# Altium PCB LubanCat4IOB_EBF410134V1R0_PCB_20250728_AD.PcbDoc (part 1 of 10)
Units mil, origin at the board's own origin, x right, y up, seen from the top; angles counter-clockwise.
Board outline 5236.21 x 4055.11 mil, 6 copper layers (TOP, GND02, ART03, PWR04, GND05, BOTTOM), stack 47.2 mil thick; 614 components, 490 nets, 2311 pads, 1916 vias.
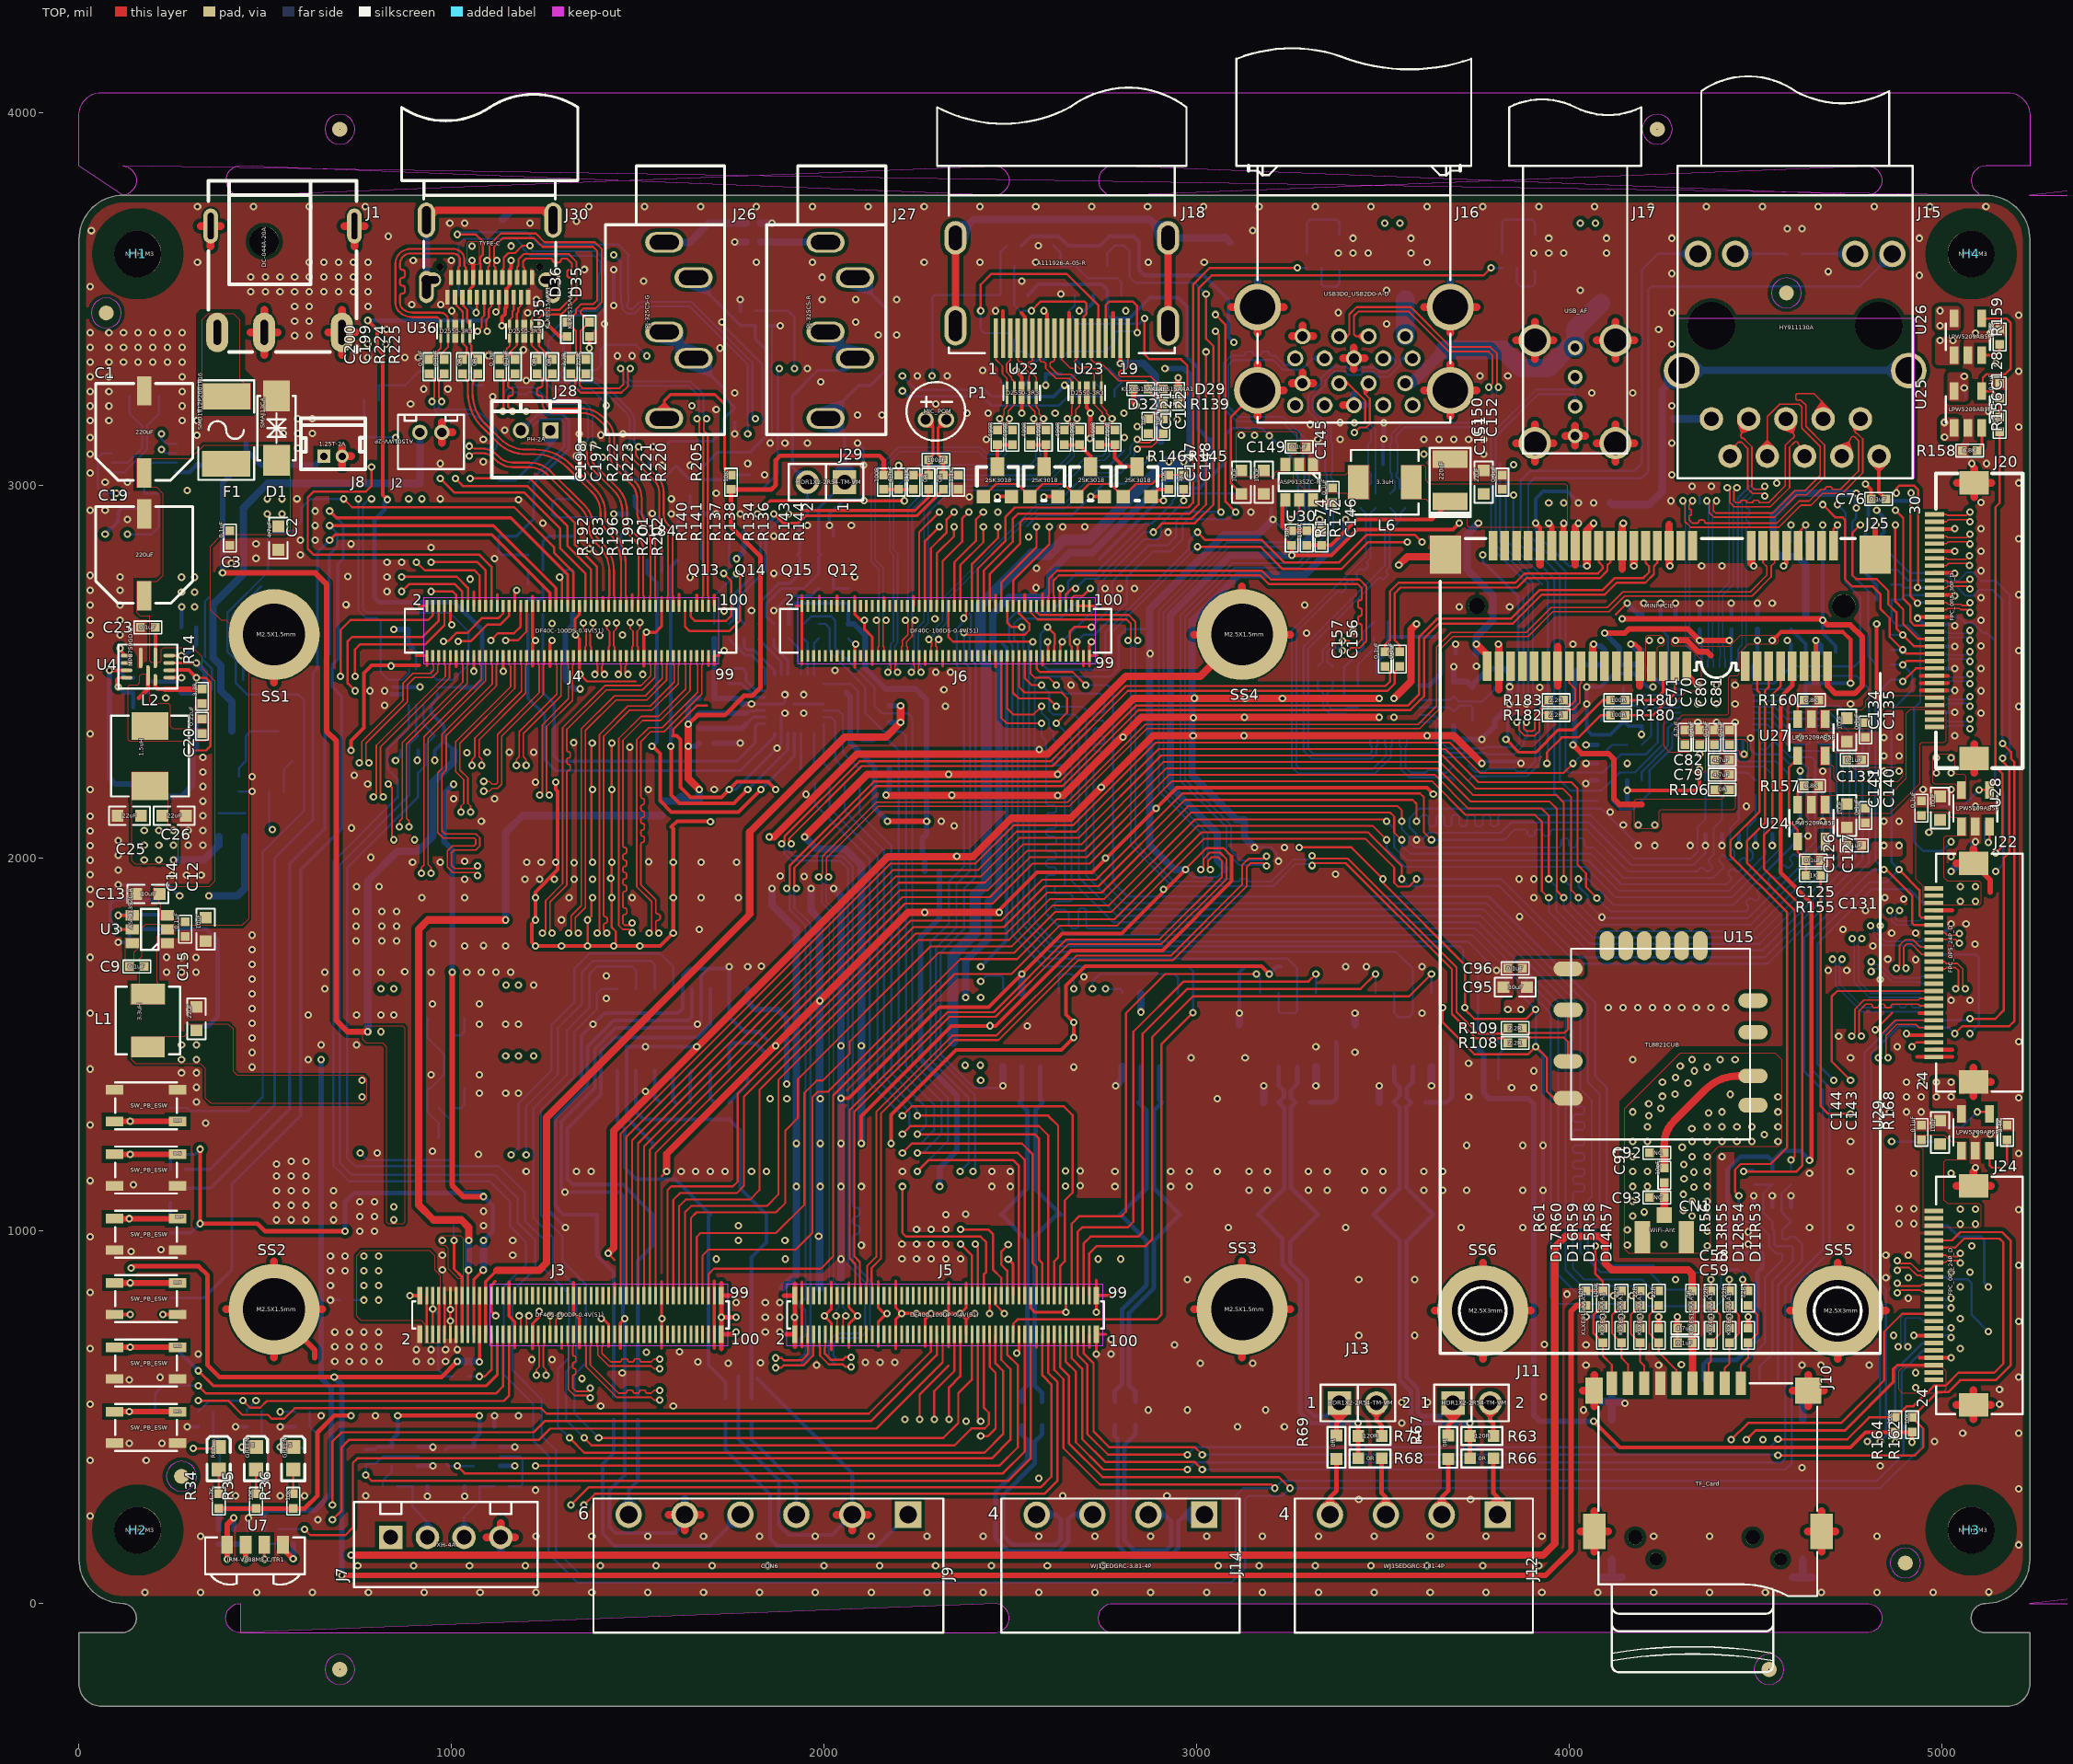
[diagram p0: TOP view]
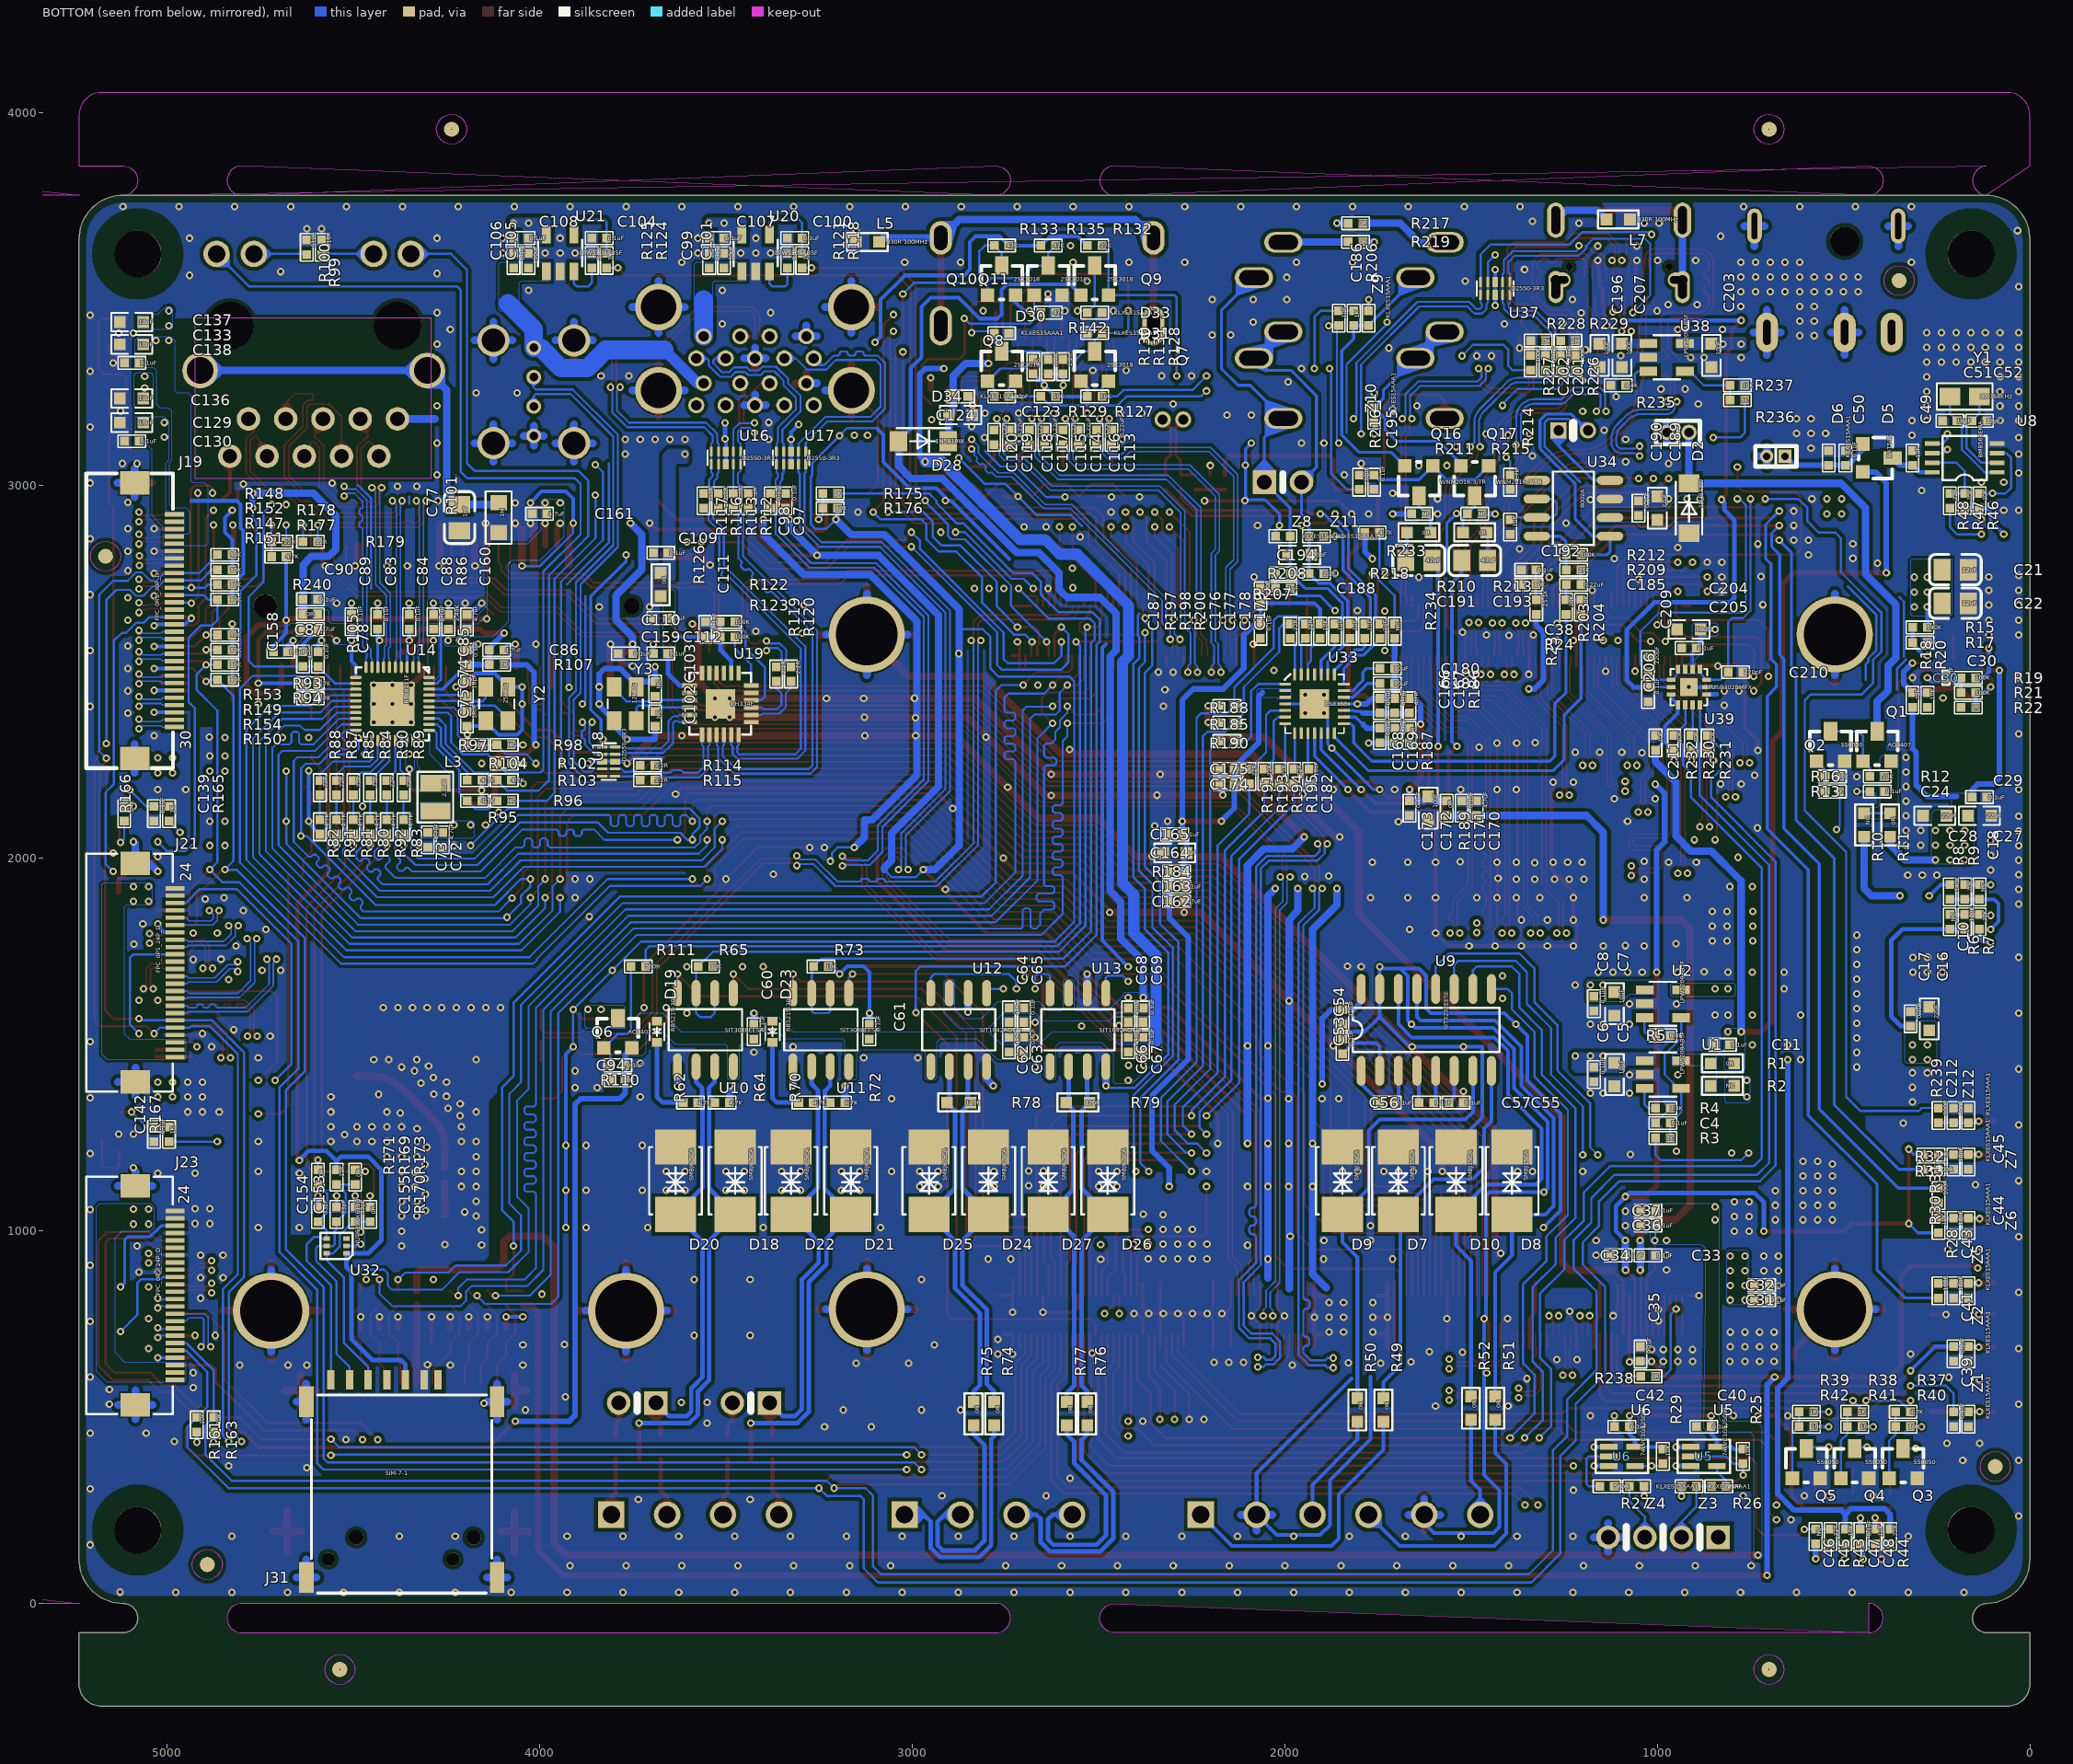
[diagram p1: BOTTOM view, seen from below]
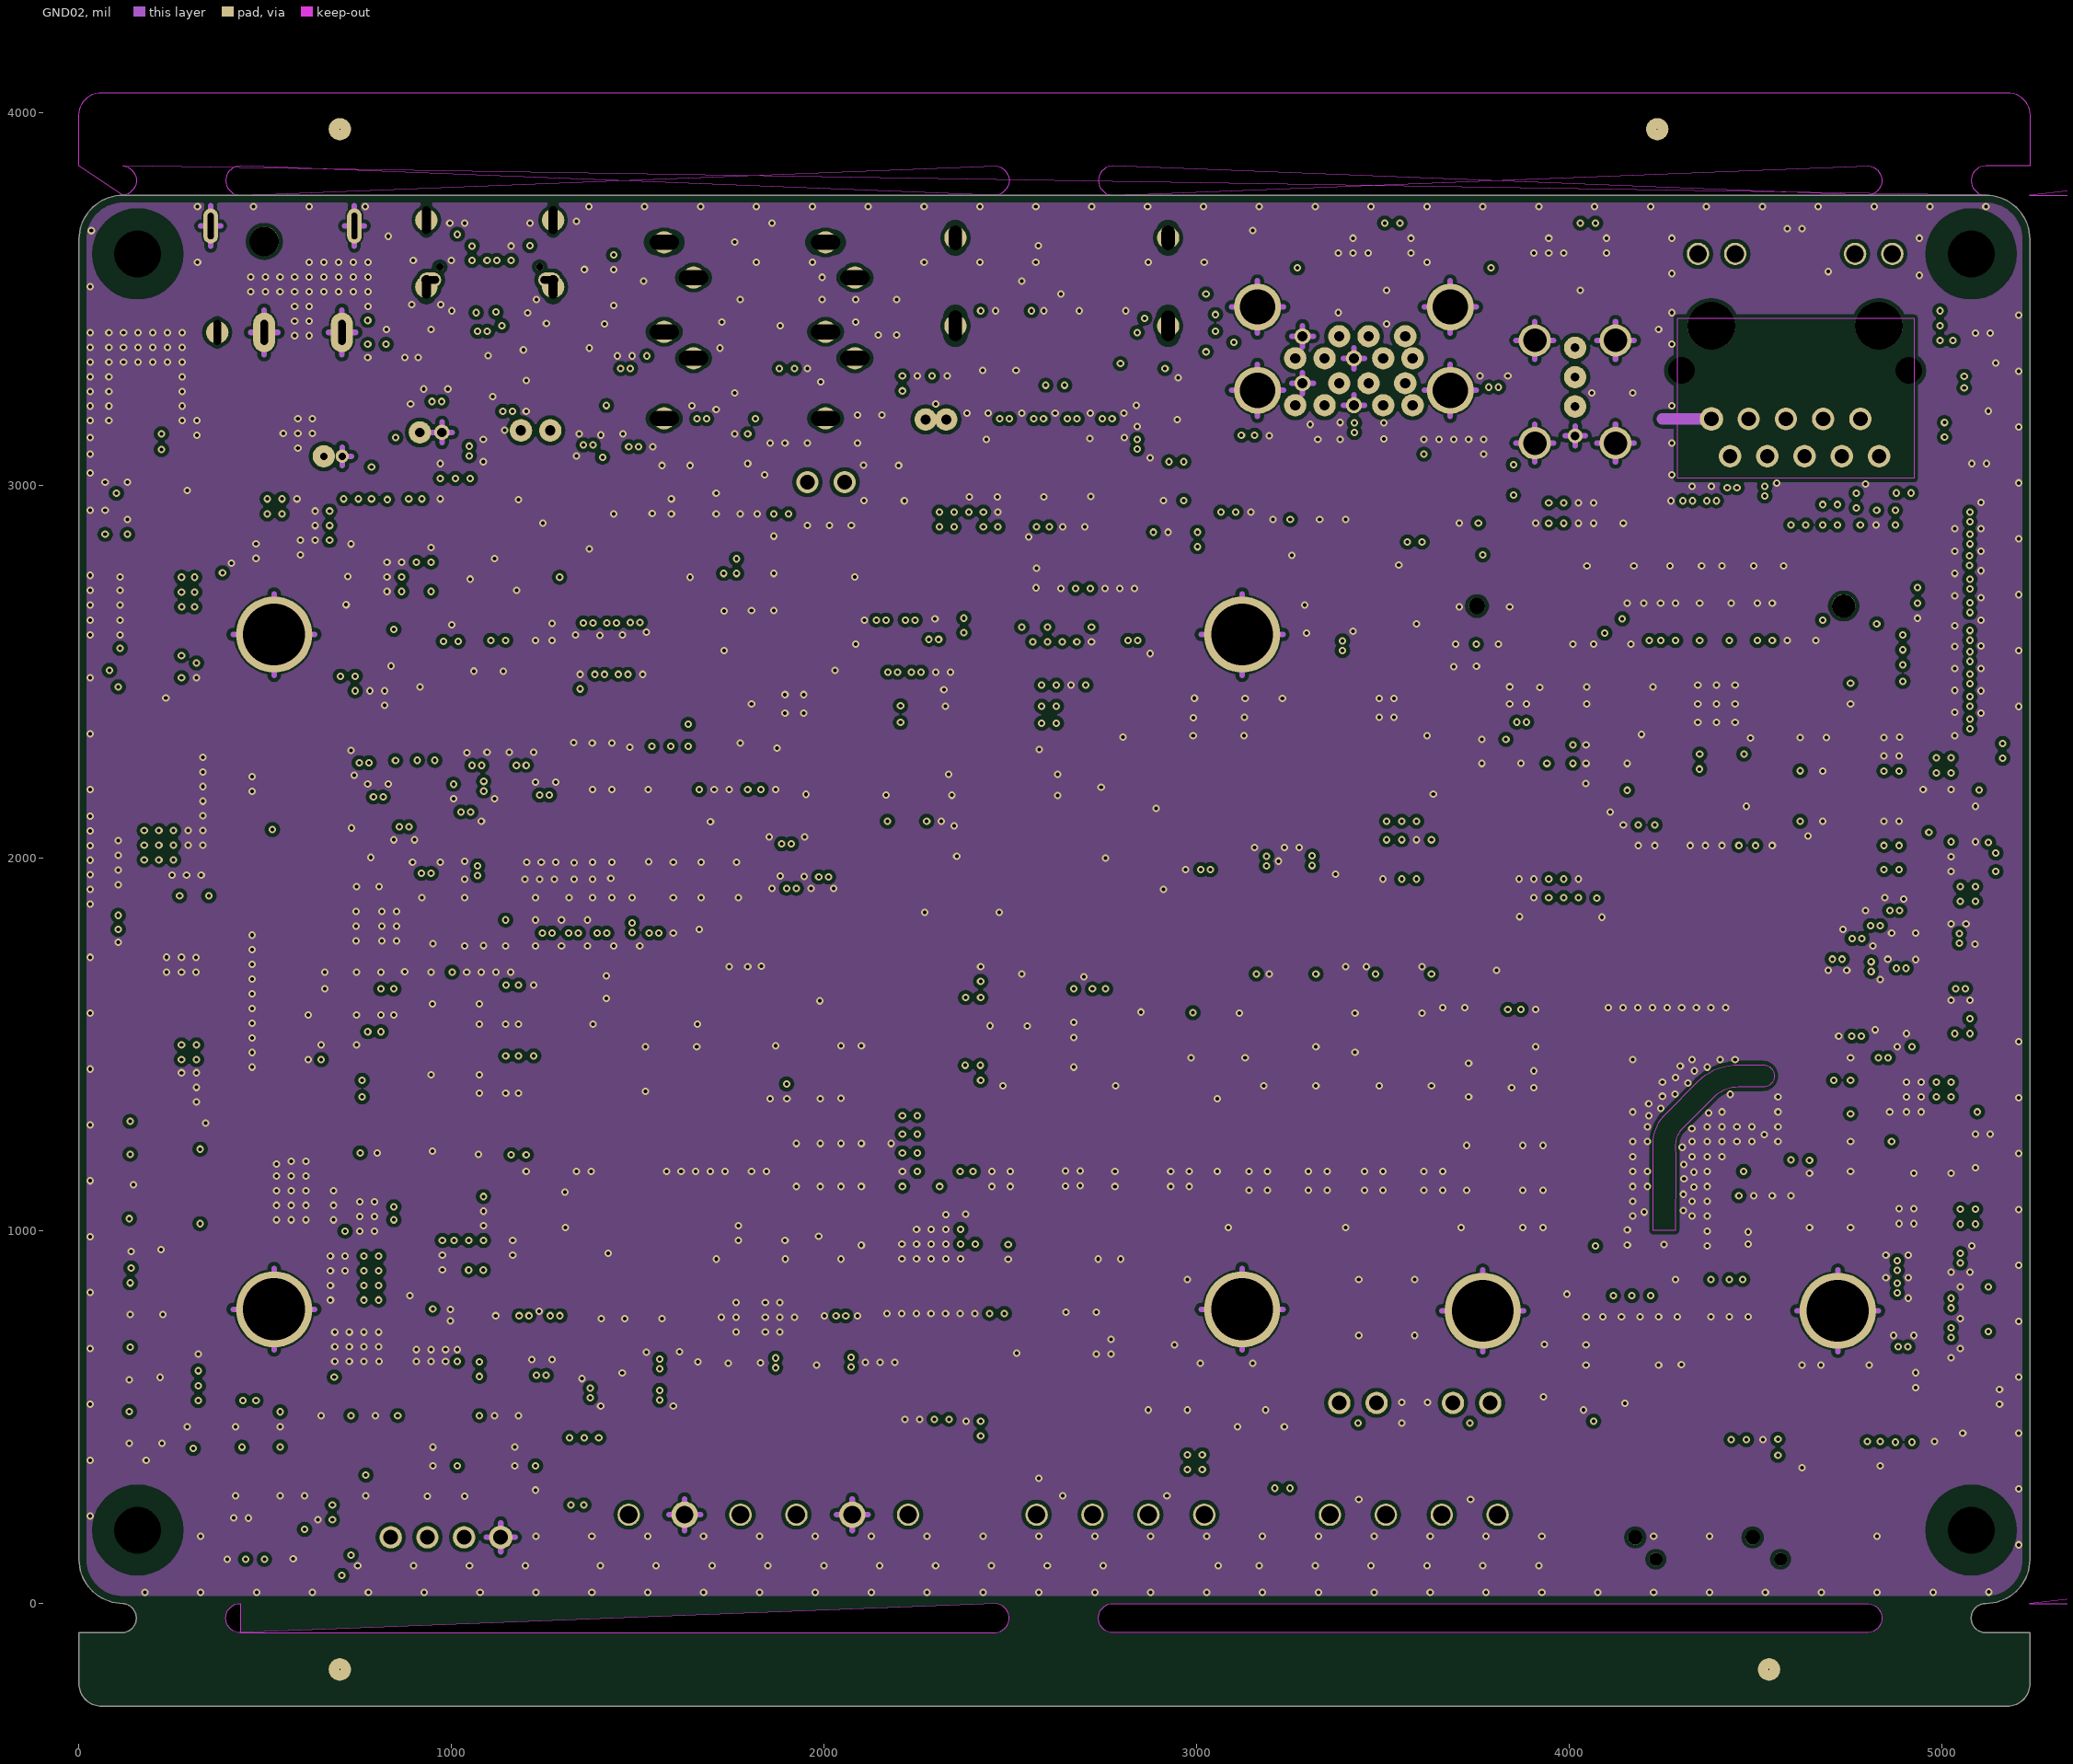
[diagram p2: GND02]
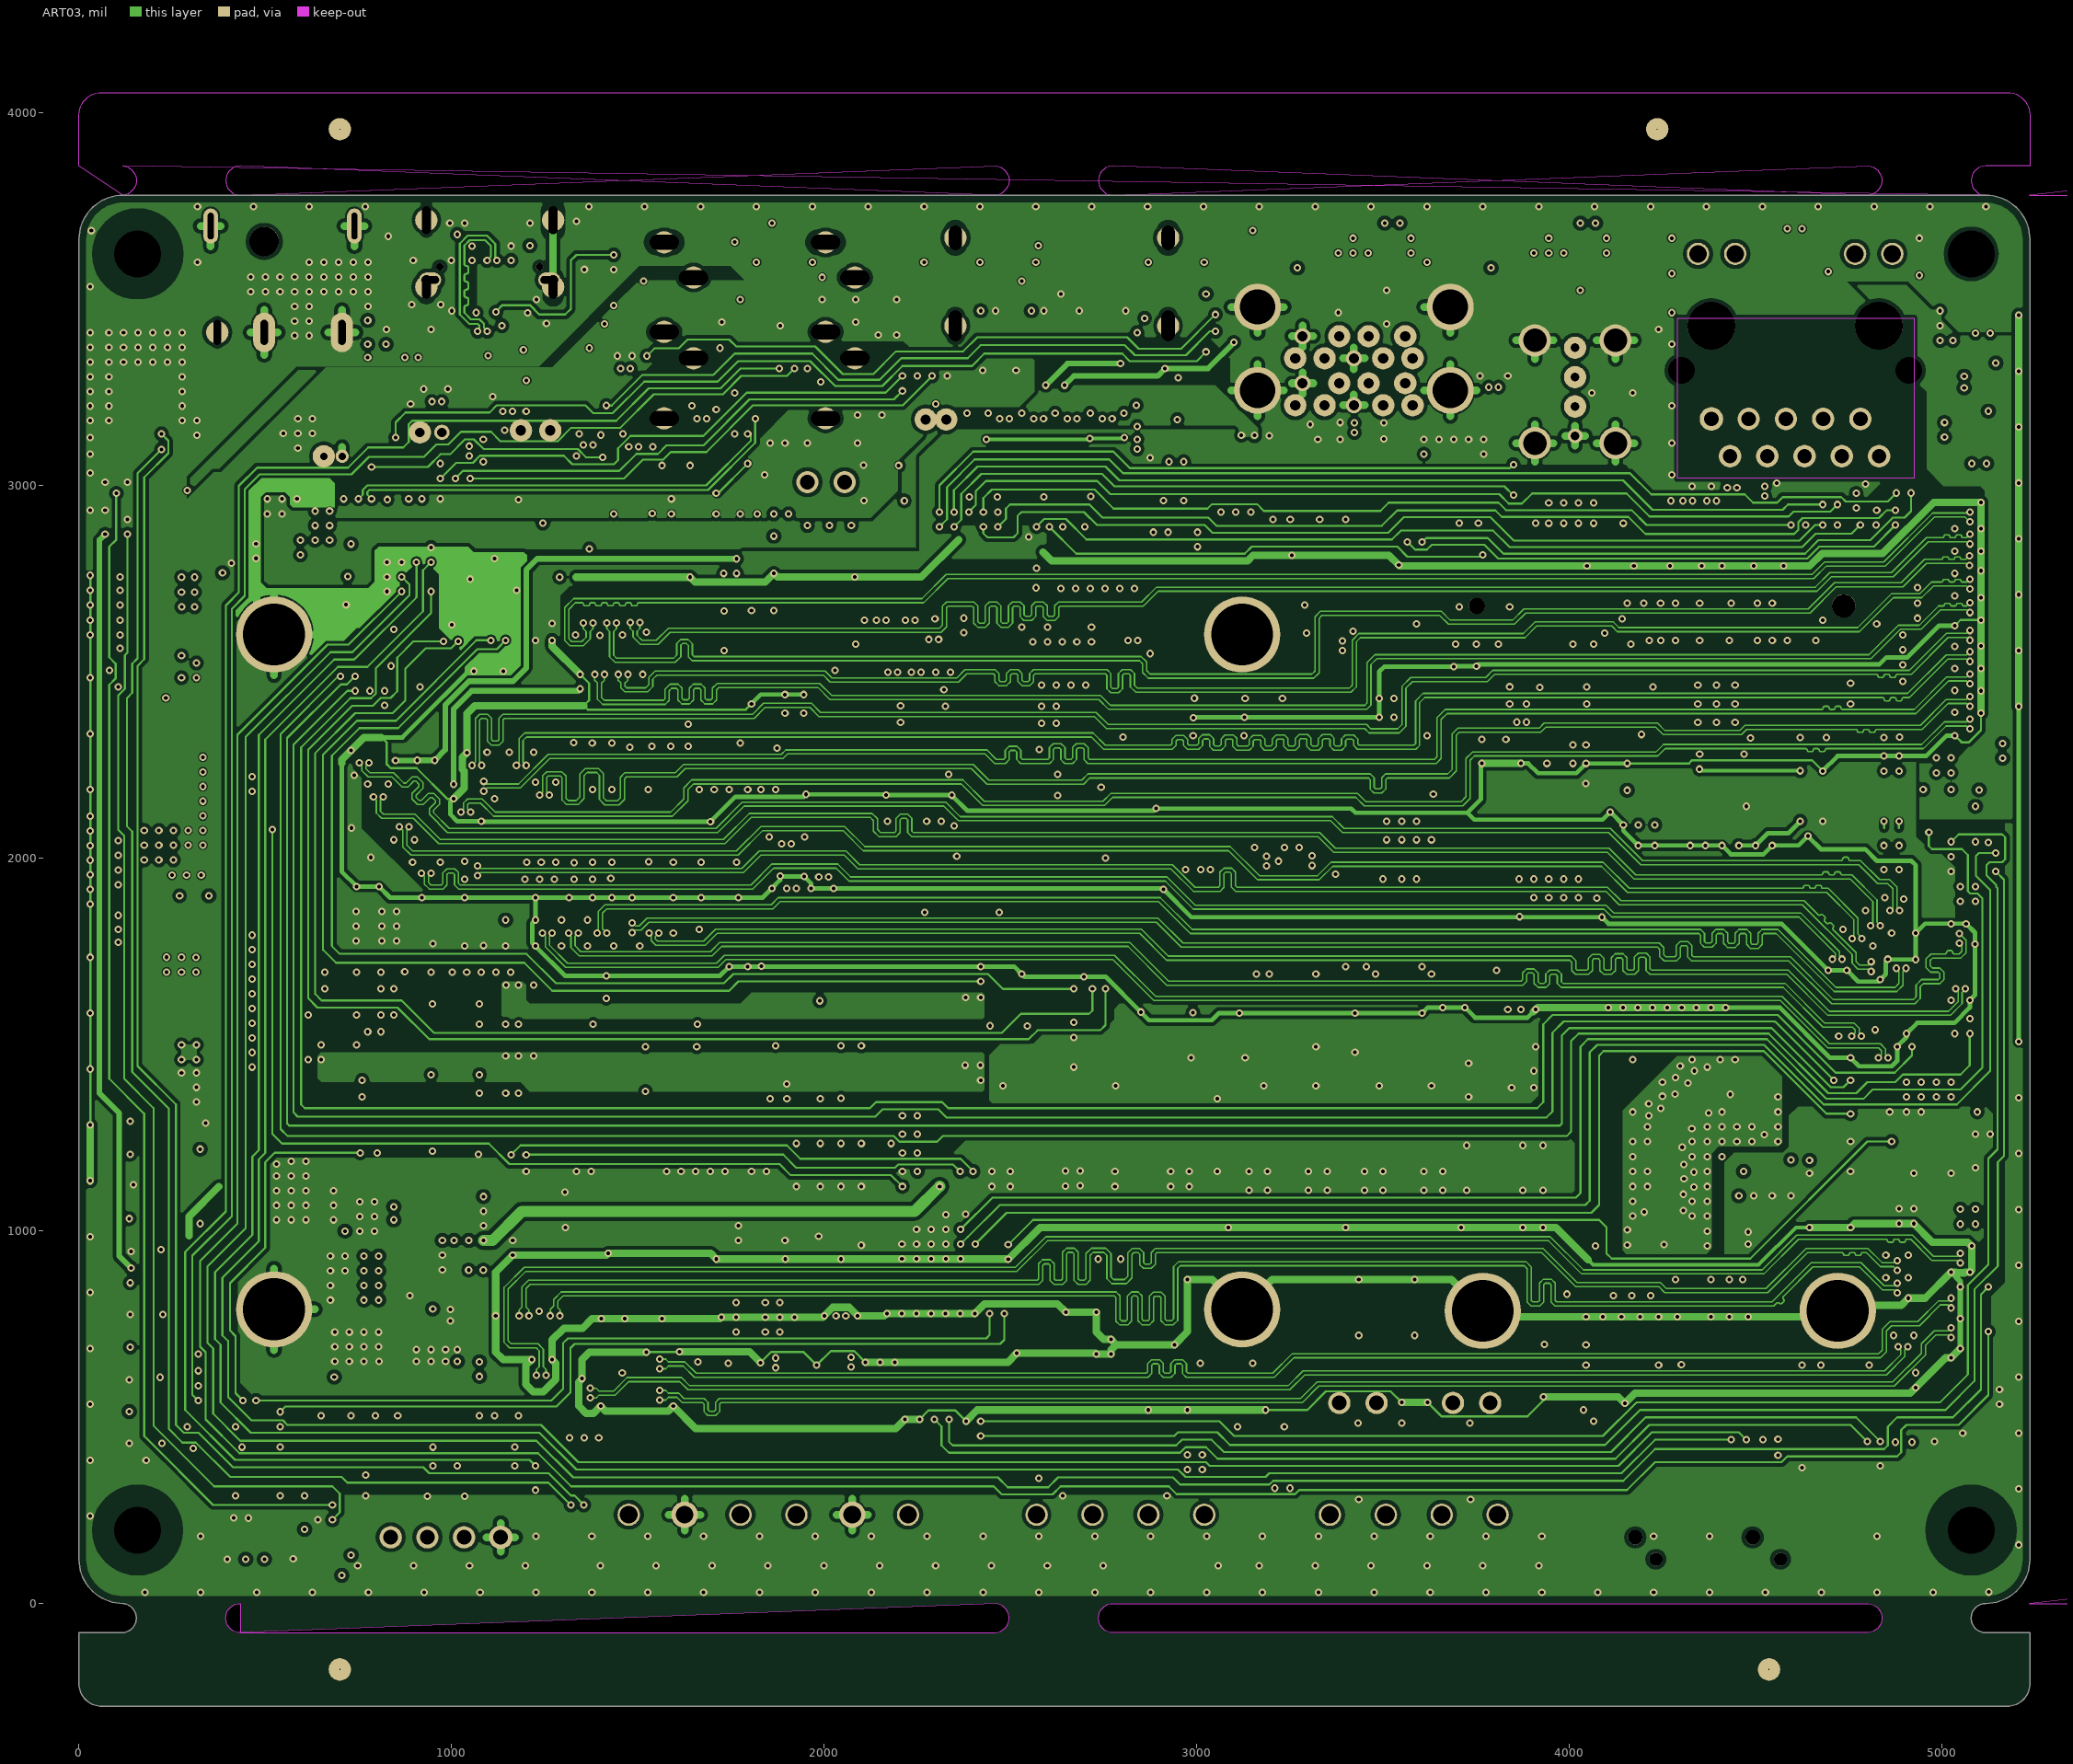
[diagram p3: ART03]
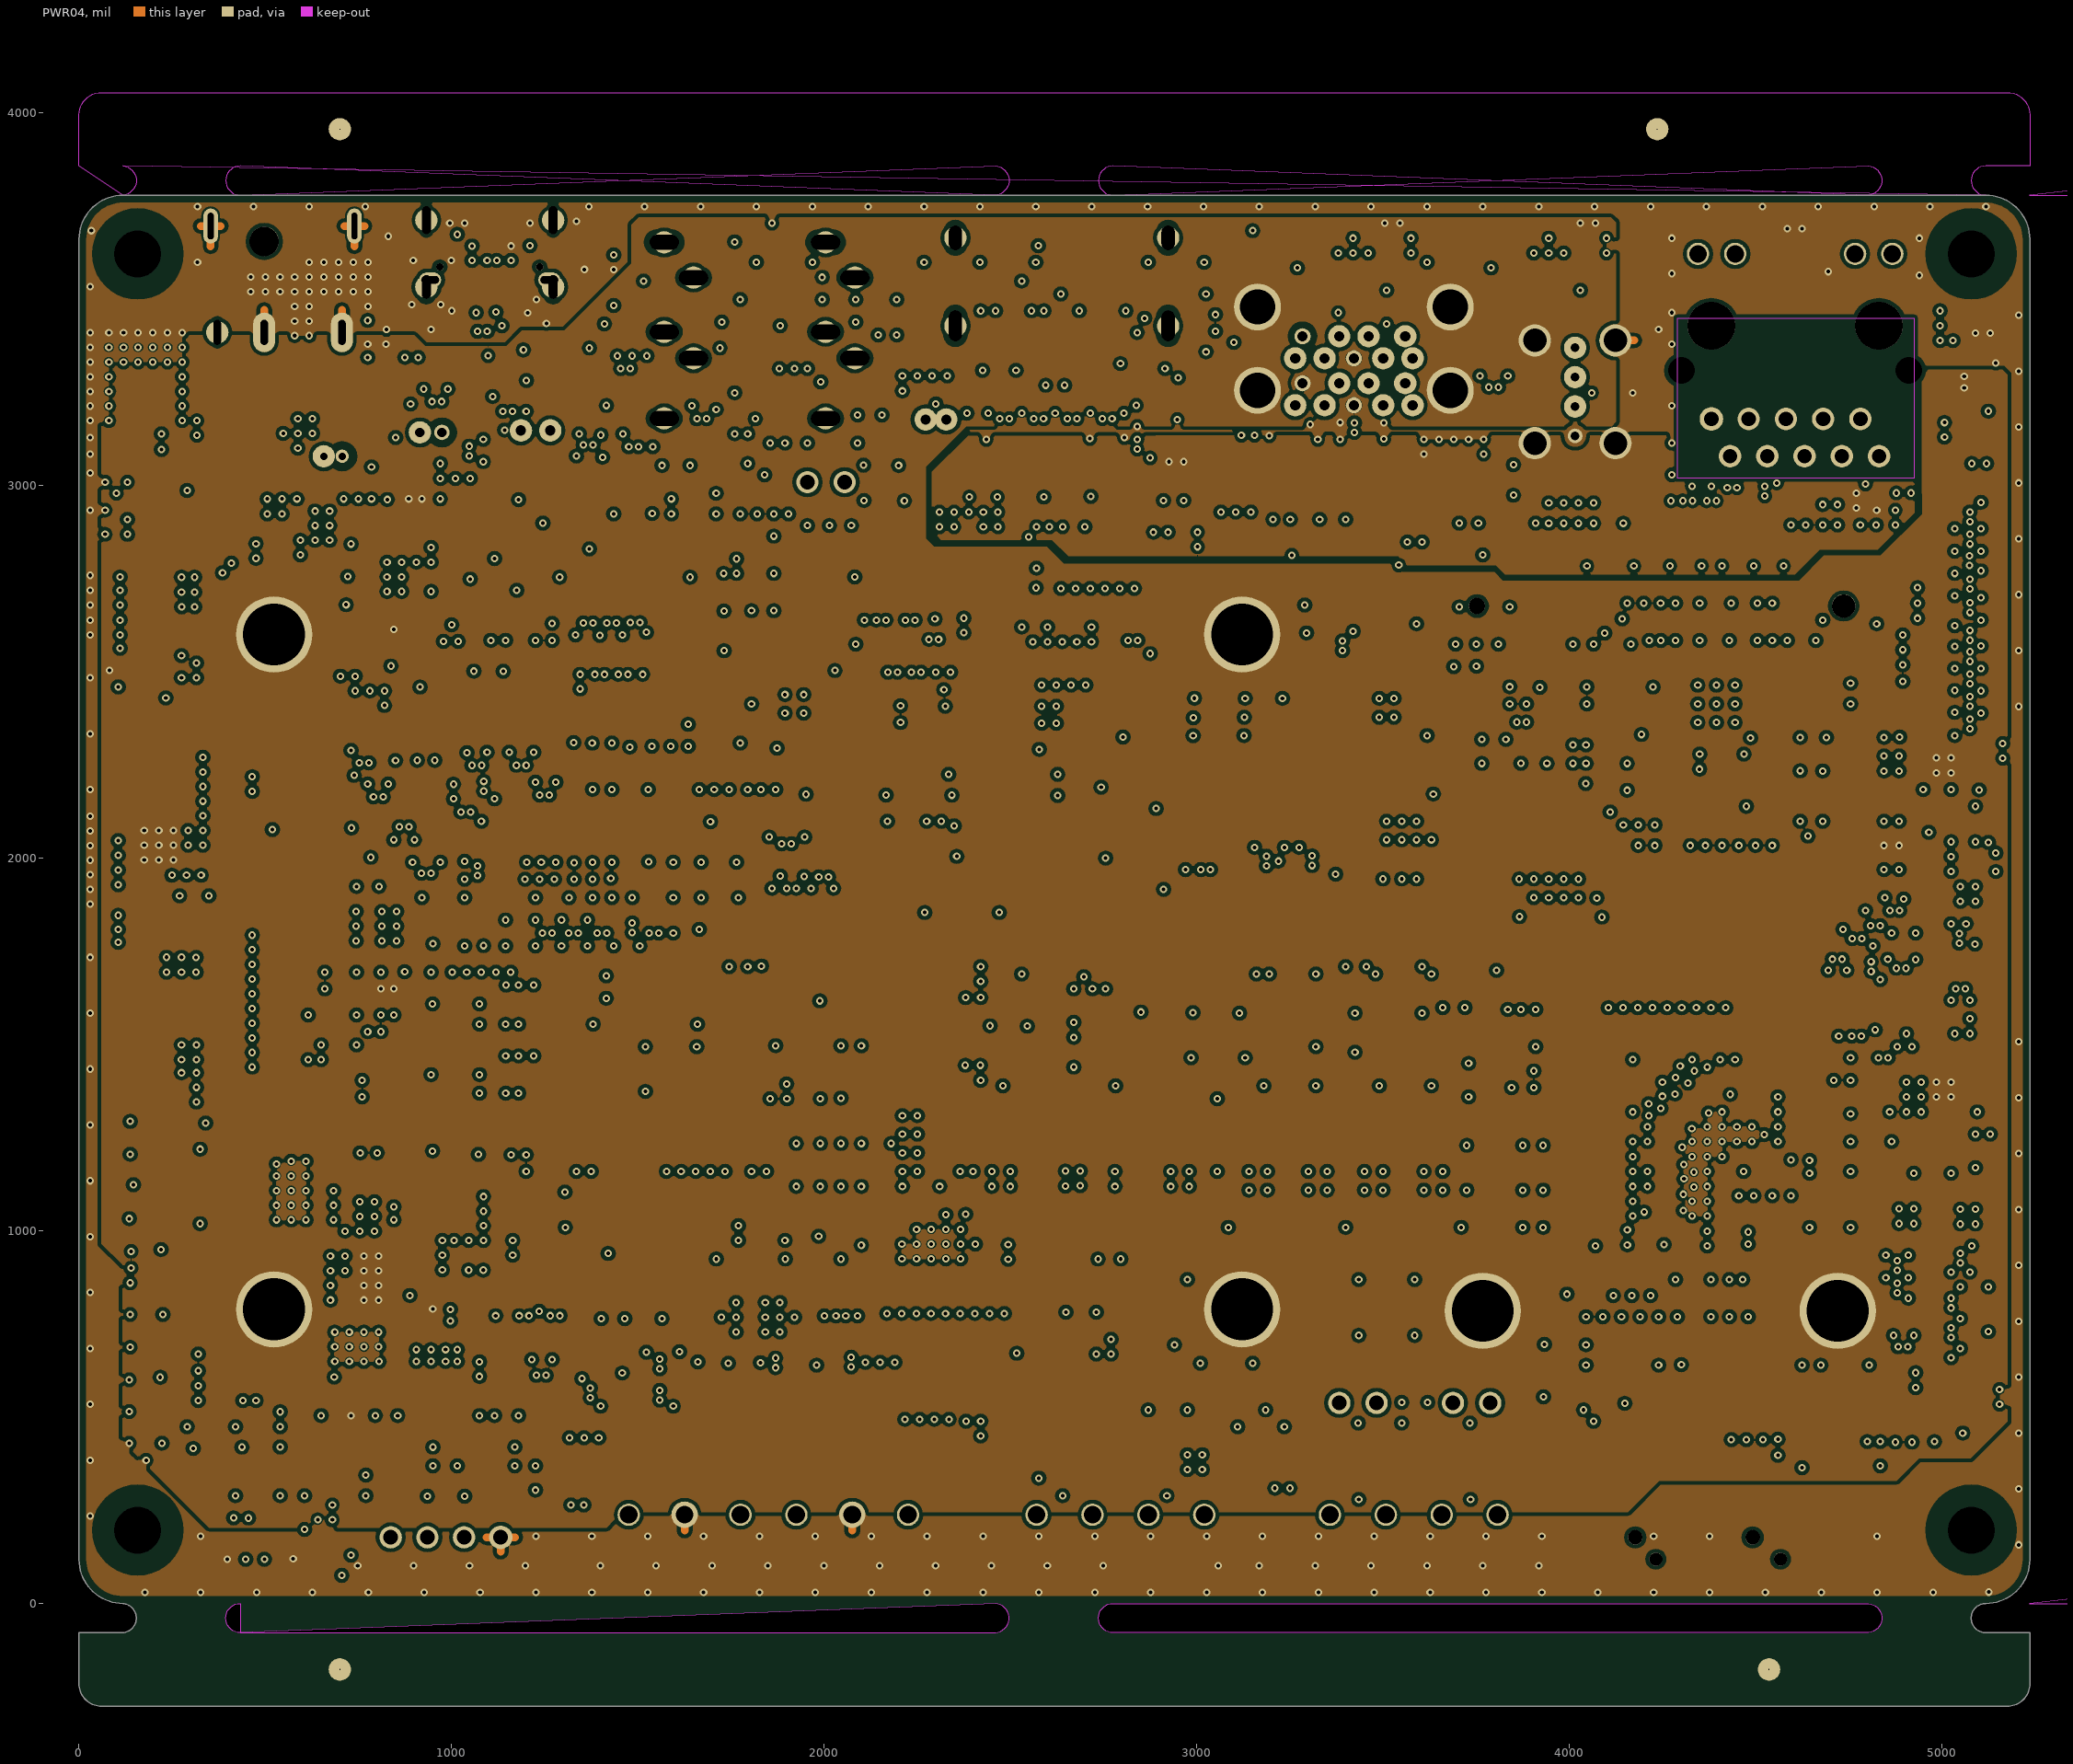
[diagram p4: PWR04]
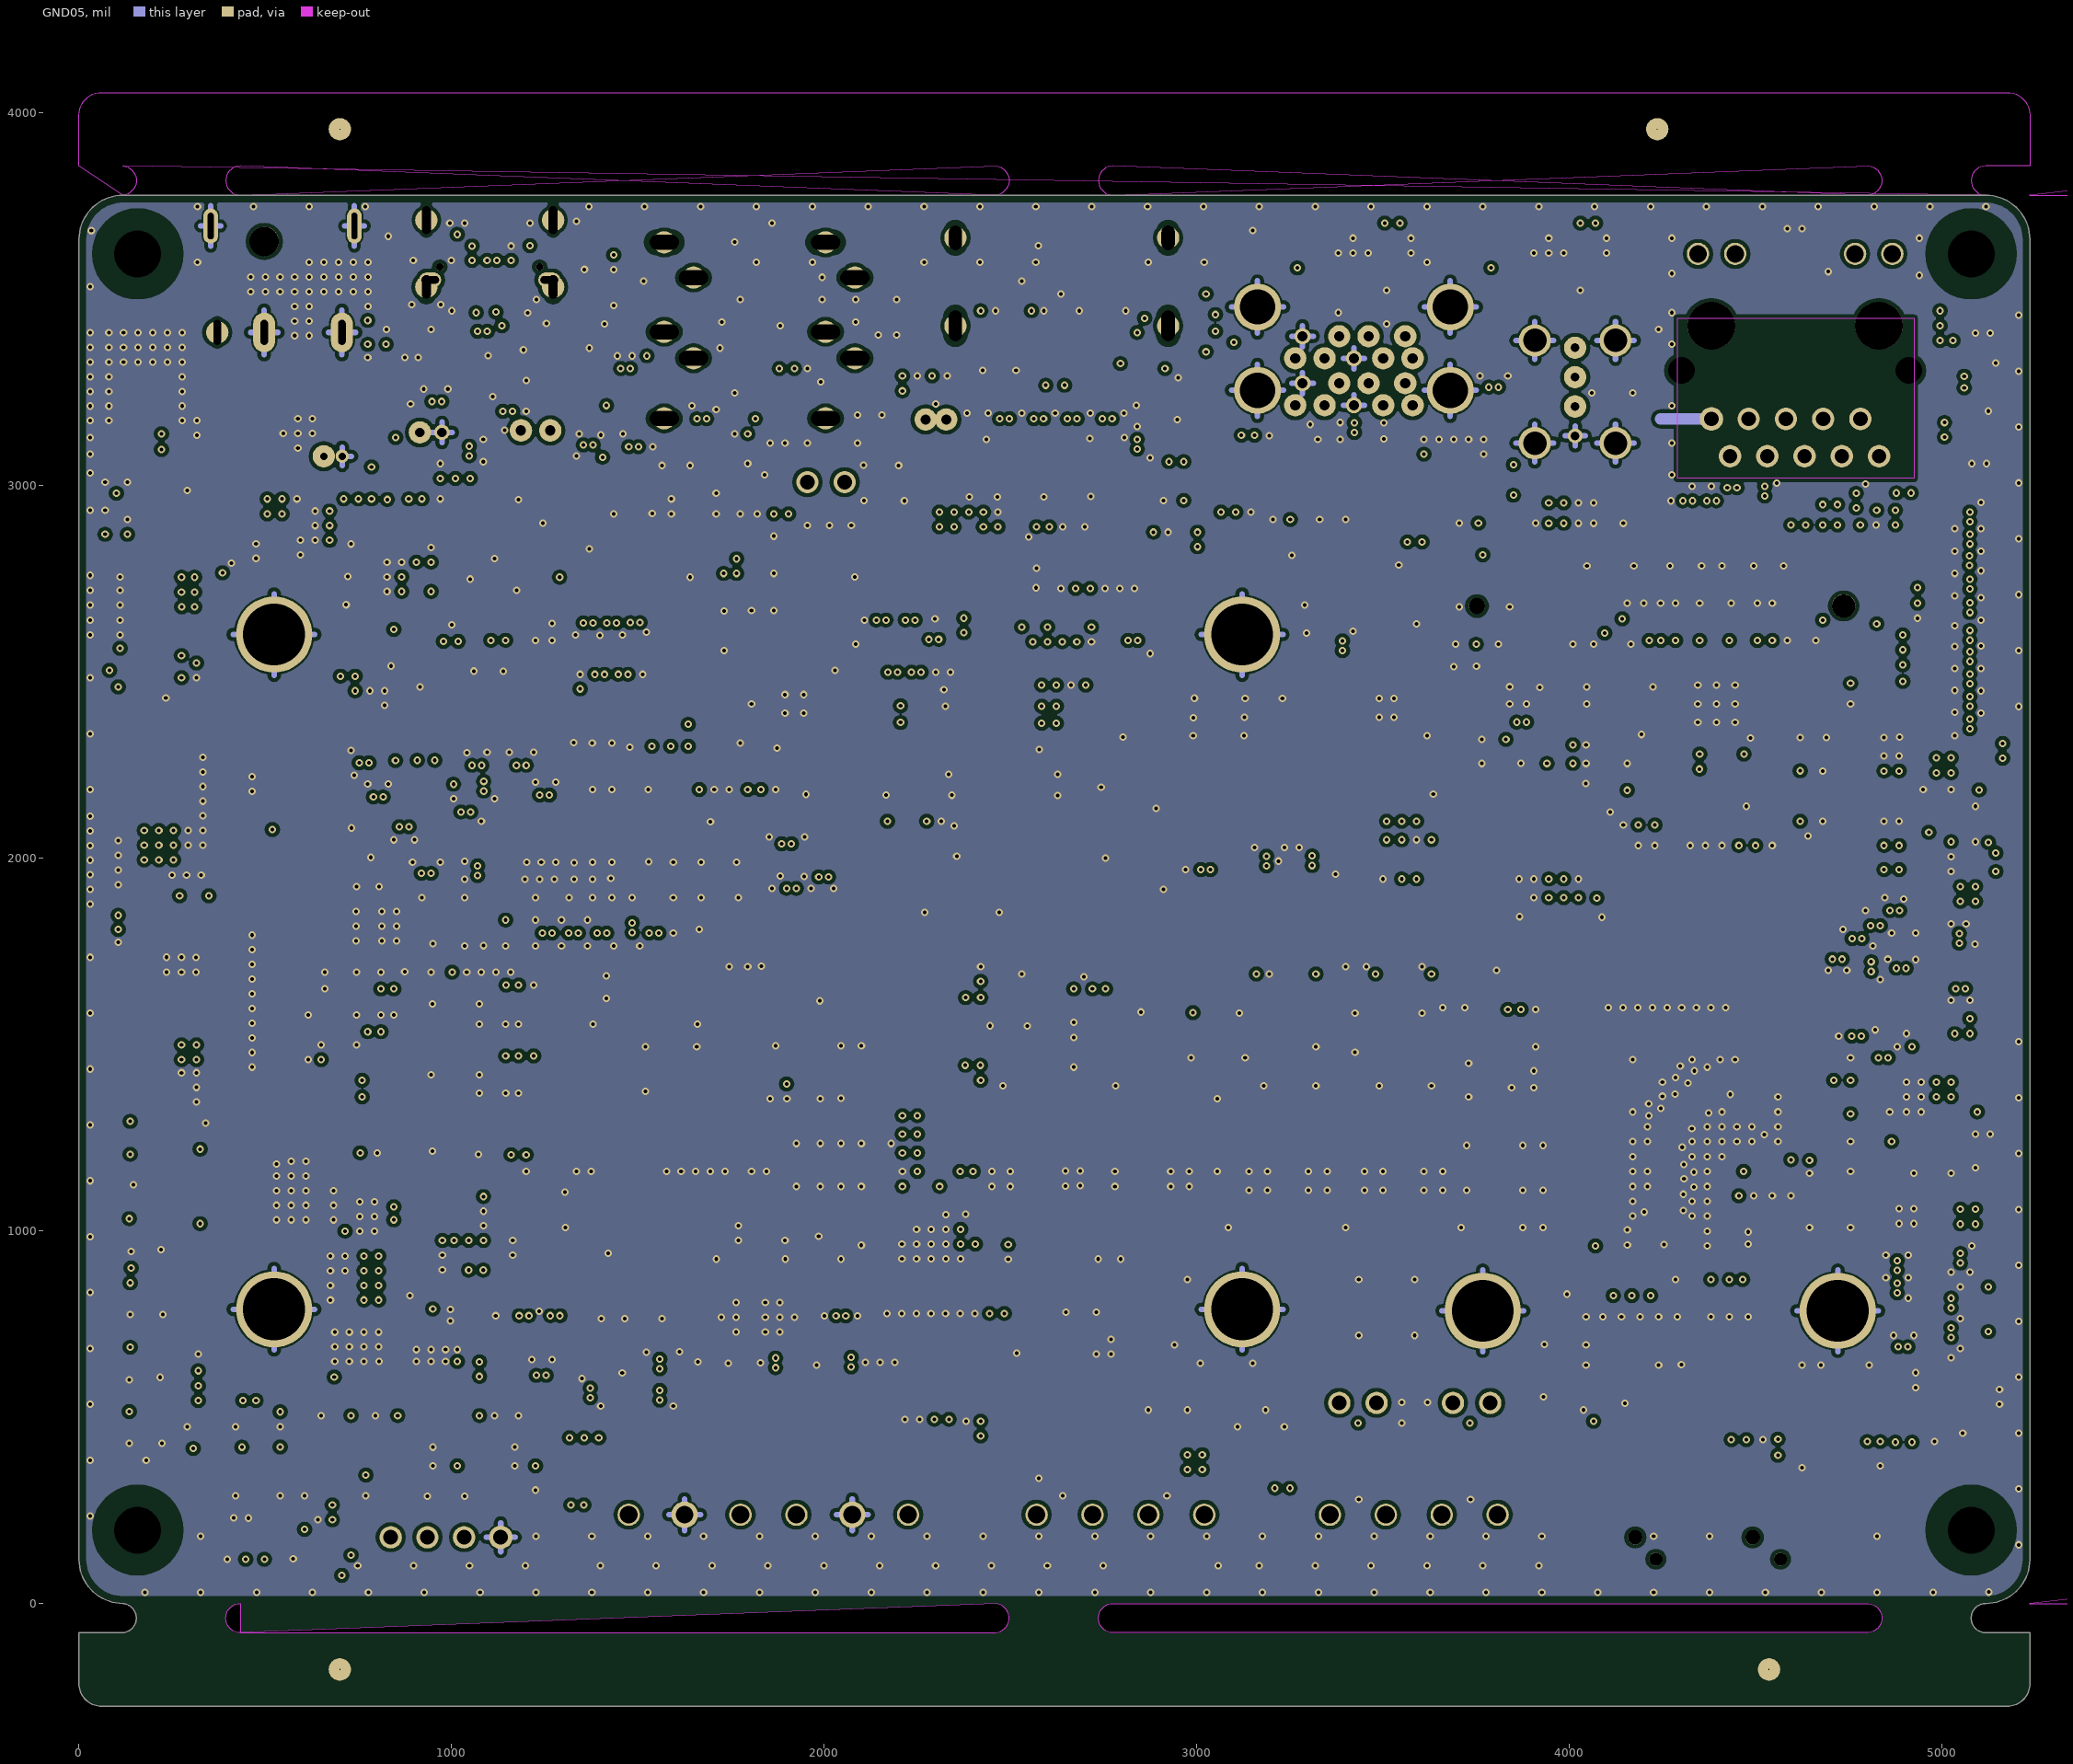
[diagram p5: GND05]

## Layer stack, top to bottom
Top Solder: solder mask 0.4, Solder Resist, Dk 3.5
TOP: signal copper 1.2
Dielectric 1: core 8, FR-4, Dk 4.5
GND02: signal copper 1.2
Dielectric2: core 8, FR-4, Dk 4.5
ART03: signal copper 1.2
Dielectric3: core 8, FR-4, Dk 4.5
PWR04: signal copper 1.2
Dielectric4: core 8, FR-4, Dk 4.5
GND05: signal copper 1.2
Dielectric5: core 8, FR-4, Dk 4.5
BOTTOM: signal copper 1.2
Bottom Solder: solder mask 0.4, Solder Resist, Dk 3.5

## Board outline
5176.21,-275.59 60,-275.59 cw(c60,-215.59) 0,-215.59 0,-78.74 118.11,-78.74 ccw(c113.95,-39.37) 118.11,0 cw(c118.11,118.11) 0,118.11 0,3661.41 cw(c118.11,3661.41) 118.11,3779.52 5118.1,3779.52 cw(c5118.1,3661.41) 5236.21,3661.41 5236.21,118.11 cw(c5118.1,118.11) 5118.1,0 ccw(c5118.1,-39.37) 5118.1,-78.74 5236.21,-78.74 5236.21,-215.59 cw(c5176.21,-215.59)
cut-out: 4803.14,3858.26 cw(c4798.98,3818.89) 2775.59,3858.26 ccw(c2775.59,3818.89)
cut-out: 2460.62,3858.26 cw(c2456.47,3818.89) 433.07,3858.26 ccw(c433.07,3818.89)
cut-out: 433.07,-78.74 cw(c433.07,-39.37) 433.07,-78.74 2460.62,-78.74 ccw(c2456.47,-39.37)
cut-out: 4803.14,0 cw(c4798.98,-39.37) 2775.59,-78.74 cw(c2775.59,-39.37)
cut-out: 118.11,3858.26 cw(c113.95,3818.89) 0,3858.26 0,3995.11 cw(c60,3995.11) 5176.21,4055.11 cw(c5176.21,3995.11) 5236.21,3858.26 5118.1,3858.26 ccw(c5118.1,3818.89)
cut-out: 5345.24,3767.56 5345.24,3791.18 5235,3779.37 6022.4,3779.37
cut-out: 5345.24,-12.44 5345.24,11.18 5235,-0.63 6022.4,-0.63

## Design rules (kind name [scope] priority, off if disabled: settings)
Clearance [All] p1: gap=10 ignorepadtopadclearanceinfootprint=FALSE except(0: Arc-Hole Track-Hole SMDPad-Hole THPad-Hole Via-Hole Fill-Hole Poly-Hole Region-Hole Text-Hole)
DiffPairsRouting [All] p1: maxlimit=10 minlimit=10 mostfreqgap=10 toplayer_minwidth=15 toplayer_maxwidth=15 toplayer_prefwidth=15 midlayer1_minwidth=15 midlayer1_maxwidth=15 midlayer1_prefwidth=15 midlayer2_minwidth=15 midlayer2_maxwidth=15 midlayer2_prefwidth=15 midlayer3_minwidth=15 midlayer3_maxwidth=15 midlayer3_prefwidth=15 midlayer4_minwidth=15 midlayer4_maxwidth=15 midlayer4_prefwidth=15 bottomlayer_minwidth=15 bottomlayer_maxwidth=15 bottomlayer_prefwidth=15 maxuncoupledlength=500
PlaneConnect [All] p1: planeconnectstyle=Direct reliefexpansion=20 reliefentries=4 reliefconductorwidth=10 reliefairgap=10
PolygonConnect [All] p1: connectstyle=Direct reliefconductorwidth=10 reliefentries=4 polygonreliefangle="90 Angle" airgapwidth=10
RoomDefinition RoomsKeepin1 [All vs False] p1: confinementstyle=ConfineIn formatcopy=TRUE lockcomponents=FALSE outline 5118.1,3739.52 5124.91,3739.22 5131.66,3738.33 5138.32,3736.86 5144.82,3734.81 5151.11,3732.2 5157.15,3729.06 5162.9,3725.39 5168.31,3721.25 5173.33,3716.64 5177.94,3711.62 5182.08,3706.21 5185.75,3700.47 5188.89,3694.42 5191.5,3688.13 5193.55,3681.63 5195.02,3674.97 5195.91,3668.22 5196.21,3661.41 5196.21,118.11 5195.91,111.3 5195.02,104.55 5193.55,97.89 5191.5,91.39 5188.89,85.1 5185.75,79.06 5182.08,73.31 5177.94,67.9 5173.33,62.88 5168.31,58.27 5162.9,54.13 5157.15,50.46 5151.11,47.32 5144.82,44.71 5138.32,42.66 5131.66,41.19 5124.91,40.3 5118.1,40 118.11,40 111.3,40.3 104.55,41.19 97.89,42.66 91.39,44.71 85.1,47.32 79.06,50.46 73.31,54.13 67.9,58.27 62.88,62.88 58.27,67.9 54.13,73.31 50.46,79.06 47.32,85.1 44.71,91.39 42.66,97.89 41.19,104.55 40.3,111.3 40,118.11 40,3661.41 40.3,3668.22 41.19,3674.97 42.66,3681.63 44.71,3688.13 47.32,3694.42 50.46,3700.47 54.13,3706.21 58.27,3711.62 62.88,3716.64 67.9,3721.25 73.31,3725.39 79.06,3729.06 85.1,3732.2 91.39,3734.81 97.89,3736.86 104.55,3738.33 111.3,3739.22 118.11,3739.52 5118.1,3739.52
RoomDefinition RoomsKeepin0 [All vs False] p2: confinementstyle=ConfineIn formatcopy=TRUE lockcomponents=FALSE outline 5118.1,3739.52 5124.91,3739.22 5131.66,3738.33 5138.32,3736.86 5144.82,3734.81 5151.11,3732.2 5157.15,3729.06 5162.9,3725.39 5168.31,3721.25 5173.33,3716.64 5177.94,3711.62 5182.08,3706.21 5185.75,3700.47 5188.89,3694.42 5191.5,3688.13 5193.55,3681.63 5195.02,3674.97 5195.91,3668.22 5196.21,3661.41 5196.21,118.11 5195.91,111.3 5195.02,104.55 5193.55,97.89 5191.5,91.39 5188.89,85.1 5185.75,79.06 5182.08,73.31 5177.94,67.9 5173.33,62.88 5168.31,58.27 5162.9,54.13 5157.15,50.46 5151.11,47.32 5144.82,44.71 5138.32,42.66 5131.66,41.19 5124.91,40.3 5118.1,40 118.11,40 111.3,40.3 104.55,41.19 97.89,42.66 91.39,44.71 85.1,47.32 79.06,50.46 73.31,54.13 67.9,58.27 62.88,62.88 58.27,67.9 54.13,73.31 50.46,79.06 47.32,85.1 44.71,91.39 42.66,97.89 41.19,104.55 40.3,111.3 40,118.11 40,3661.41 40.3,3668.22 41.19,3674.97 42.66,3681.63 44.71,3688.13 47.32,3694.42 50.46,3700.47 54.13,3706.21 58.27,3711.62 62.88,3716.64 67.9,3721.25 73.31,3725.39 79.06,3729.06 85.1,3732.2 91.39,3734.81 97.89,3736.86 104.55,3738.33 111.3,3739.22 118.11,3739.52 5118.1,3739.52
RoutingVias [All] p1: holewidth=28 width=50 viastyle="Through Hole" minholewidth=28 minwidth=50 maxholewidth=28 maxwidth=50
SolderMaskExpansion [All] p1: expansion=4 istentingtop=FALSE
Width [All] p1: maxlimit=10 minlimit=10 preferedwidth=10 impedanceprofiledriven=TRUE minimp=50.170000 maximp=63.220000 favimp=46.610000
28 further rules are at their usual default settings.

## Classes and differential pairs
net class DIFF90OHM: USB30_SSRXN USB30_SSRXP
net class DIFF85OHM: PCIE20_0_RXN PCIE20_0_RXP PCIE20_0_TXN PCIE20_0_TXP PE_TXN PE_TXP
net class C_EARTH: N15752445 N18241743 N18479746 N18480944
net class C_ANLOG: MIC1_L MIC1_R MIC2_L MIC2_R N18315822 N18315825 N18315828 N18315831 N18479761 N18479774 N18639472 N18639500 N18645225 N18645232 N18645288 N18645295 OUT1_L OUT1_R OUT2_L OUT2_R
net class DIFF100HOM: MDIN0_PHY MDIN1_PHY MDIN2_PHY MDIN3_PHY MDIP0_PHY MDIP1_PHY MDIP2_PHY MDIP3_PHY MIPI_CSI0_RX_CLK0N MIPI_CSI0_RX_CLK0P MIPI_CSI0_RX_CLK1N MIPI_CSI0_RX_CLK1P MIPI_CSI0_RX_D0N MIPI_CSI0_RX_D0P MIPI_CSI0_RX_D1N MIPI_CSI0_RX_D1P MIPI_CSI0_RX_D2N MIPI_CSI0_RX_D2P MIPI_CSI0_RX_D3N MIPI_CSI0_RX_D3P MIPI_DPHY0_RX_CLKN MIPI_DPHY0_RX_CLKP MIPI_DPHY0_RX_D0N MIPI_DPHY0_RX_D0P MIPI_DPHY0_RX_D1N MIPI_DPHY0_RX_D1P MIPI_DPHY0_RX_D2N MIPI_DPHY0_RX_D2P MIPI_DPHY0_RX_D3N MIPI_DPHY0_RX_D3P MIPI_DPHY0_TX_CLKN MIPI_DPHY0_TX_CLKP MIPI_DPHY0_TX_D0N MIPI_DPHY0_TX_D0P MIPI_DPHY0_TX_D1N MIPI_DPHY0_TX_D1P MIPI_DPHY0_TX_D2N MIPI_DPHY0_TX_D2P MIPI_DPHY0_TX_D3N MIPI_DPHY0_TX_D3P MIPI_DPHY1_RX_CLKN MIPI_DPHY1_RX_CLKP MIPI_DPHY1_RX_D0N MIPI_DPHY1_RX_D0P MIPI_DPHY1_RX_D1N MIPI_DPHY1_RX_D1P MIPI_DPHY1_RX_D2N MIPI_DPHY1_RX_D2P MIPI_DPHY1_RX_D3N MIPI_DPHY1_RX_D3P MIPI_DPHY1_TX_CLKN MIPI_DPHY1_TX_CLKP MIPI_DPHY1_TX_D0N MIPI_DPHY1_TX_D0P MIPI_DPHY1_TX_D1N MIPI_DPHY1_TX_D1P MIPI_DPHY1_TX_D2N MIPI_DPHY1_TX_D2P MIPI_DPHY1_TX_D3N MIPI_DPHY1_TX_D3P PCIE20_0_CLKN PCIE20_0_CLKP
net class GND: GND
net class 50OHM: GMAC1_MDC GMAC1_MDIO GMAC1_TXCLK GMAC1_TXD0 GMAC1_TXD1 GMAC1_TXD2 GMAC1_TXD3 GMAC1_TXEN
net class 3W: CAM0_NRST CAM1_NRST CAM2_NRST CAM3_NRST CTP0_RST CTP1_RST FAN_PWM GMAC1_RSTN LCD0_RST LCD1_RST PCIE20X1_2_PERSTN_M0 RTC_32K_IN
net class C_POWER: 1V05_AVDD_PHY 1V05_PHY 3V3_DVDD_PHY 3V3_IMAGE0 3V3_IMAGE1 3V3_WLAN 5V0_CAM0/1 5V0_CAM2/3 5V0_IMAGE0 5V0_IMAGE1 HDMI_5V N18464854 SIM_VDD USB30_VBUS VBUS_TYPEC VCC3V3_SYS VCC5V0_SYS VCC_1V8_S0 VCC_3V3_S3 VCC_3V3_SD VCC_12V VCCA1V8_CODEC VCCA3V3_CODEC VCCA_1V8_S0 VCCA_3V3_S0 VDD_3V3 VDD_5V
differential pair DIFF_SS_TX: +USB30_SSTXN -USB30_SSTXP
differential pair DIFF_USB30_SSRX: +USB30_SSRXN -USB30_SSRXP
differential pair DIFF_USB20_HOST1_D: +USB20_HOST1_DM -USB20_HOST1_DP
differential pair DP3: +USB20_HOST0_DM -USB20_HOST0_DP
differential pair DIFF_SSTX_2: +TYPEC0_SSTX2N/DP0_TX3N -TYPEC0_SSTX2P/DP0_TX3P
differential pair DIFF_SSTX_1: +TYPEC0_SSTX1N/DP0_TX1N -TYPEC0_SSTX1P/DP0_TX1P
differential pair DIFF_SSRX_2: +TYPEC0_SSRX2N/DP0_TX2N -TYPEC0_SSRX2P/DP0_TX2P
differential pair DIFF_SSRX_1: +TYPEC0_SSRX1N/DP0_TX0N -TYPEC0_SSRX1P/DP0_TX0P
differential pair DIFF_TYPEC0_AUX: +TYPEC0_SBU1/DP0_AUXP -TYPEC0_SBU2/DP0_AUXN
differential pair DIFF_OTG_D: +TYPEC0_OTG_DM -TYPEC0_OTG_DP
differential pair DIFF_TYPEC_CC: +TYPEC_CC1 -TYPEC_CC2
differential pair DIFF_HDMI_TX0_D3: +TX_D3N_PORT -TX_D3P_PORT
differential pair DIFF_HDMI_TX0_D2: +TX_D2N_PORT -TX_D2P_PORT
differential pair DIFF_HDMI_TX0_D1: +TX_D1N_PORT -TX_D1P_PORT
differential pair DIFF_HDMI_TX0_D0: +TX_D0N_PORT -TX_D0P_PORT
differential pair DIFF_SSTX_2: +SSTX_2P -TYPEC0_SSTX2N/DP0_TX3N
differential pair DIFF_SSTX_2: +SSTX_2N -SSTX_2P
differential pair DIFF_SSTX_1: +SSTX_1P -TYPEC0_SSTX1N/DP0_TX1N
differential pair DIFF_SSTX_1: +SSTX_1N -SSTX_1P
differential pair DIFF_SSRX_2: +SSRX_2P -TYPEC0_SSRX2N/DP0_TX2N
differential pair DIFF_SSRX_2: +SSRX_2N -SSRX_2P
differential pair DIFF_SSRX_1: +SSRX_1P -TYPEC0_SSRX1N/DP0_TX0N
differential pair DIFF_SSRX_1: +SSRX_1N -SSRX_1P
differential pair DIFF_SS_TX: +SS_TXP -USB30_SSTXN
differential pair DIFF_SS_TX: +SS_TXN -SS_TXP
differential pair DIFF_TYPEC0_AUX: +SBU_2 -TYPEC0_SBU1/DP0_AUXP
differential pair DIFF_TYPEC0_AUX: +SBU_1 -SBU_2
differential pair PE_TX: +PE_TXN -PE_TXP
differential pair PCIE20_0_TX: +PCIE20_0_TXN -PCIE20_0_TXP
differential pair DIFF_PCIE20_0_RX: +PCIE20_0_RXN -PCIE20_0_RXP
differential pair DIFF_PCIE20_0_CLK: +PCIE20_0_CLKN -PCIE20_0_CLKP
differential pair DIFF_OTG_D: +OTG_DP -TYPEC0_OTG_DM
differential pair DIFF_OTG_D: +OTG_DM -OTG_DP
differential pair DIFF_USB20_HOST1_D: +N18057335 -USB20_HOST1_DM
differential pair DIFF_USB20_HOST1_D: +N18057325 -N18057335
differential pair DP4: +N18057251 -N18057253
differential pair DP3: +N17770942 -USB20_HOST0_DM
differential pair DP3: +N17770939 -N17770942
differential pair DIFF_MIPI_DPHY1_TX_D3: +MIPI_DPHY1_TX_D3N -MIPI_DPHY1_TX_D3P
differential pair DIFF_MIPI_DPHY1_TX_D2: +MIPI_DPHY1_TX_D2N -MIPI_DPHY1_TX_D2P
differential pair DIFF_MIPI_DPHY1_TX_D1: +MIPI_DPHY1_TX_D1N -MIPI_DPHY1_TX_D1P
differential pair DIFF_MIPI_DPHY1_TX_D0: +MIPI_DPHY1_TX_D0N -MIPI_DPHY1_TX_D0P
differential pair DIFF_MIPI_DPHY1_TX_CLK: +MIPI_DPHY1_TX_CLKN -MIPI_DPHY1_TX_CLKP
differential pair DIFF_MIPI_DPHY1_RX_D3: +MIPI_DPHY1_RX_D3N -MIPI_DPHY1_RX_D3P
differential pair DIFF_MIPI_DPHY1_RX_D2: +MIPI_DPHY1_RX_D2N -MIPI_DPHY1_RX_D2P
differential pair DIFF_MIPI_DPHY1_RX_D1: +MIPI_DPHY1_RX_D1N -MIPI_DPHY1_RX_D1P
differential pair DIFF_MIPI_DPHY1_RX_D0: +MIPI_DPHY1_RX_D0N -MIPI_DPHY1_RX_D0P
differential pair DIFF_MIPI_DPHY1_RX_CLK: +MIPI_DPHY1_RX_CLKN -MIPI_DPHY1_RX_CLKP
differential pair DIFF_MIPI_DPHY0_TX_D3: +MIPI_DPHY0_TX_D3N -MIPI_DPHY0_TX_D3P
differential pair DIFF_MIPI_DPHY0_TX_D2: +MIPI_DPHY0_TX_D2N -MIPI_DPHY0_TX_D2P
differential pair DIFF_MIPI_DPHY0_TX_D1: +MIPI_DPHY0_TX_D1N -MIPI_DPHY0_TX_D1P
differential pair DIFF_MIPI_DPHY0_TX_D0: +MIPI_DPHY0_TX_D0N -MIPI_DPHY0_TX_D0P
differential pair DIFF_MIPI_DPHY0_TX_CLK: +MIPI_DPHY0_TX_CLKN -MIPI_DPHY0_TX_CLKP
differential pair DIFF_MIPI_DPHY0_RX_D3: +MIPI_DPHY0_RX_D3N -MIPI_DPHY0_RX_D3P
differential pair DIFF_MIPI_DPHY0_RX_D2: +MIPI_DPHY0_RX_D2N -MIPI_DPHY0_RX_D2P
differential pair DIFF_MIPI_DPHY0_RX_D1: +MIPI_DPHY0_RX_D1N -MIPI_DPHY0_RX_D1P
differential pair DIFF_MIPI_DPHY0_RX_D0: +MIPI_DPHY0_RX_D0N -MIPI_DPHY0_RX_D0P
differential pair DIFF_MIPI_DPHY0_RX_CLK: +MIPI_DPHY0_RX_CLKN -MIPI_DPHY0_RX_CLKP
differential pair DIFF_MIPI_CSI0_RX_D3: +MIPI_CSI0_RX_D3N -MIPI_CSI0_RX_D3P
differential pair DIFF_MIPI_CSI0_RX_D2: +MIPI_CSI0_RX_D2N -MIPI_CSI0_RX_D2P
differential pair DIFF_MIPI_CSI0_RX_D1: +MIPI_CSI0_RX_D1N -MIPI_CSI0_RX_D1P
differential pair DIFF_MIPI_CSI0_RX_D0: +MIPI_CSI0_RX_D0N -MIPI_CSI0_RX_D0P
differential pair DIFF_MIPI_CSI0_RX_CLK1: +MIPI_CSI0_RX_CLK1N -MIPI_CSI0_RX_CLK1P
differential pair DIFF_MIPI_CSI0_RX_CLK0: +MIPI_CSI0_RX_CLK0N -MIPI_CSI0_RX_CLK0P
differential pair DIFF_MDI3_PHY: +MDIN3_PHY -MDIP3_PHY
differential pair DIFF_MDI2_PHY: +MDIN2_PHY -MDIP2_PHY
differential pair DIFF_MDI1_PHY: +MDIN1_PHY -MDIP1_PHY
differential pair DIFF_MID0_PHY: +MDIN0_PHY -MDIP0_PHY
differential pair DP4: +HUB_DP4 -N18057251
differential pair DP4: +HUB_DM4 -HUB_DP4
differential pair DP5: +HUB_DM3 -HUB_DP3
differential pair DP2: +HUB_DM2 -HUB_DP2
differential pair DP1: +HUB_DM1 -HUB_DP1
differential pair DIFF_HDMI_TX0_SBD: +HDMI_TX0_SBDN -HDMI_TX0_SBDP
differential pair DIFF_HDMI_TX0_D3: +HDMI_TX0_D3P -TX_D3N_PORT
differential pair DIFF_HDMI_TX0_D3: +HDMI_TX0_D3N -HDMI_TX0_D3P
differential pair DIFF_HDMI_TX0_D2: +HDMI_TX0_D2P -TX_D2N_PORT
differential pair DIFF_HDMI_TX0_D2: +HDMI_TX0_D2N -HDMI_TX0_D2P
differential pair DIFF_HDMI_TX0_D1: +HDMI_TX0_D1P -TX_D1N_PORT
differential pair DIFF_HDMI_TX0_D1: +HDMI_TX0_D1N -HDMI_TX0_D1P
differential pair DIFF_HDMI_TX0_D0: +HDMI_TX0_D0P -TX_D0N_PORT
differential pair DIFF_HDMI_TX0_D0: +HDMI_TX0_D0N -HDMI_TX0_D0P
differential pair DIFF_HDMI_TX0_SBD: +HDMI_EARC+ -HDMI_TX0_SBDN
differential pair DIFF_HDMI_TX0_SBD: +HDMI_EARC- -HDMI_EARC+
differential pair DP5: +B_DP3 -HUB_DM3
differential pair DP2: +B_DP2 -HUB_DM2
differential pair DP1: +B_DP1 -HUB_DM1
differential pair DP5: +B_DM3 -B_DP3
differential pair DP2: +B_DM2 -B_DP2
differential pair DP1: +B_DM1 -B_DP1

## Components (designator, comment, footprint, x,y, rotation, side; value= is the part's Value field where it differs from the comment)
C1 "CAP_EC6P3_220UF" EC6P3 175,3144.37 r180 top
C2 "CAP_NP_C0603_DISCRETE_4.7UF" C0603#1 535,2859.37 r270 top
C3 "CAP_NP_C0402_DISCRETE_0.1UF" C0402#1 405,2859.37 r270 top
C4 "CAP_NP_C0402_DISCRETE_0.1UF" C0402#1 985,1289.37 r0 bottom
C5 "CAP_NP_C0603_DISCRETE_10UF" C0603#1 1115,1419.37 r270 bottom
C6 "CAP_NP_C0402_DISCRETE_0.1UF" C0402#1 1170,1419.37 r270 bottom
C7 "CAP_NP_C0603_DISCRETE_10UF" C0603#1 1115,1609.37 r270 bottom
C8 "CAP_NP_C0402_DISCRETE_0.1UF" C0402#1 1170,1609.37 r270 bottom
C9 "CAP_NP_C0402_DISCRETE_0.1UF" C0402#1 155,1709.37 r0 top
C10 "CAP_NP_C0402_DISCRETE_NC" C0402#1 215,1829.37 r90 bottom
C11 "CAP_NP_C0402_DISCRETE_0.1UF" C0402#1 825,1499.37 r0 bottom
C12 "CAP_NP_C0603_DISCRETE_10UF" C0603#1 340,1809.37 r270 top
C13 "CAP_NP_C0603_DISCRETE_10UF" C0603#1 185,1904.37 r180 top
C14 "CAP_NP_C0402_DISCRETE_0.1UF" C0402#1 285,1809.37 r270 top
C15 "CAP_NP_C0603_DISCRETE_22UF" C0603#1 315,1569.37 r90 top
C16 "CAP_NP_C0603_DISCRETE_22UF" C0603#1 270,1569.37 r90 bottom
C17 "CAP_NP_C0402_DISCRETE_0.1UF" C0402#1 320,1569.37 r90 bottom
C18 "CAP_NP_C0402_DISCRETE_NC" C0402#1 135,1909.37 r270 bottom
C19 "CAP_EC6P3_220UF" EC6P3 175,2814.37 r180 top
C20 "CAP_NP_C0402_DISCRETE_0.22UF" C0402#1 330,2354.37 r270 top
C21 "CAP_NP_C0805_DISCRETE_22UF" C0805#1 200,2774.37 r0 bottom
C22 "CAP_NP_C0805_DISCRETE_22UF" C0805#1 200,2684.37 r0 bottom
C23 "CAP_NP_C0402_DISCRETE_0.1UF" C0402#1 185,2619.37 r180 top
C24 "CAP_NP_C0402_DISCRETE_0.1UF" C0402#1 410,2179.37 r0 bottom
C25 "CAP_NP_C0603_DISCRETE_22UF" C0603#1 135,2114.37 r180 top
C26 "CAP_NP_C0603_DISCRETE_22UF" C0603#1 255,2114.37 r0 top
C27 "CAP_NP_C0603_DISCRETE_22UF" C0603#2 135,2114.37 r0 bottom
C28 "CAP_NP_C0603_DISCRETE_22UF" C0603#1 255,2114.37 r0 bottom
C29 "CAP_NP_C0402_DISCRETE_0.1UF" C0402#2 135,2164.37 r0 bottom
C30 "CAP_NP_C0201_DISCRETE_1UF" C0201 225,2484.37 r90 bottom
C31 "CAP_NP_C0402_DISCRETE_0.1UF" C0402#2 720,814.37 r0 bottom
C32 "CAP_NP_C0402_DISCRETE_0.1UF" C0402#2 720,854.37 r0 bottom
C33 "CAP_NP_C0402_DISCRETE_0.1UF" C0402#2 1025,934.37 r0 bottom
C34 "CAP_NP_C0402_DISCRETE_0.1UF" C0402#1 1105,934.37 r0 bottom
C35 "CAP_NP_C0402_DISCRETE_0.1UF" C0402#1 1045,669.37 r90 bottom
C36 "CAP_NP_C0402_DISCRETE_0.1UF" C0402#1 1025,1014.37 r0 bottom
C37 "CAP_NP_C0402_DISCRETE_0.1UF" C0402#1 1025,1054.37 r0 bottom
C38 "CAP_NP_C0402_DISCRETE_0.1UF" C0402#1 1345,2774.37 r0 bottom
C39 "CAP_NP_C0402_DISCRETE_0.1UF" C0402#1 205,494.37 r270 bottom
C40 "CAP_NP_C0402_DISCRETE_0.1UF" C0402#1 875,474.37 r0 bottom
C41 "CAP_NP_C0402_DISCRETE_0.1UF" C0402#1 205,670 r270 bottom
C42 "CAP_NP_C0402_DISCRETE_0.1UF" C0402#1 1095,474.37 r0 bottom
C43 "CAP_NP_C0402_DISCRETE_10NF" C0402#1 205,839.37 r270 bottom
C44 "CAP_NP_C0402_DISCRETE_10NF" C0402#1 205,1014.37 r270 bottom
C45 "CAP_NP_C0402_DISCRETE_10NF" C0402#1 205,1185 r270 bottom
C46 "CAP_NP_C0402_DISCRETE_NC" C0402#1 575,179.37 r270 bottom
C47 "CAP_NP_C0402_DISCRETE_0.1UF" C0402#1 455,179.37 r90 bottom
C48 "CAP_NP_C0402_DISCRETE_1UF" C0402#1 415,179.37 r90 bottom
C49 "CAP_NP_C0402_DISCRETE_1UF" C0402#1 315,3074.37 r90 bottom
C50 "CAP_NP_C0402_DISCRETE_0.1UF" C0402#1 495,3074.37 r90 bottom
C51 "CAP_NP_C0402_DISCRETE_18PF" C0402#1 215,3174.37 r0 bottom
C52 "CAP_NP_C0402_DISCRETE_18PF" C0402#2 135,3174.37 r0 bottom
C53 "CAP_NP_C0402_DISCRETE_0.1UF" C0402#1 1845,1494.37 r90 bottom
C54 "CAP_NP_C0402_DISCRETE_4.7UF" C0402#1 1845,1574.37 r270 bottom
C55 "CAP_NP_C0402_DISCRETE_0.1UF" C0402#2 1540,1344.37 r0 bottom
C56 "CAP_NP_C0402_DISCRETE_0.1UF" C0402#1 1725,1344.37 r0 bottom
C57 "CAP_NP_C0402_DISCRETE_0.1UF" C0402#1 1620,1344.37 r0 bottom
C58 "CAP_NP_C0402_DISCRETE_4.7UF" C0402#1 4310,739.37 r180 top
C59 "CAP_NP_C0402_DISCRETE_0.1UF" C0402#1 4310,699.37 r180 top
C60 "CAP_NP_C0402_DISCRETE_0.1UF" C0402#1 3425,1534.37 r90 bottom
C61 "CAP_NP_C0402_DISCRETE_0.1UF" C0402#1 3115,1534.37 r90 bottom
C62 "CAP_NP_C0402_DISCRETE_4.7UF" C0402#1 2740,1499.37 r90 bottom
C63 "CAP_NP_C0402_DISCRETE_0.1UF" C0402#1 2700,1499.37 r90 bottom
C64 "CAP_NP_C0402_DISCRETE_4.7UF" C0402#1 2740,1579.37 r270 bottom
C65 "CAP_NP_C0402_DISCRETE_0.1UF" C0402#1 2700,1579.37 r270 bottom
C66 "CAP_NP_C0402_DISCRETE_4.7UF" C0402#1 2420,1499.37 r90 bottom
C67 "CAP_NP_C0402_DISCRETE_0.1UF" C0402#1 2380,1499.37 r90 bottom
C68 "CAP_NP_C0402_DISCRETE_4.7UF" C0402#1 2420,1579.37 r270 bottom
C69 "CAP_NP_C0402_DISCRETE_0.1UF" C0402#1 2380,1579.37 r270 bottom
C70 "CAP_NP_C0402_DISCRETE_0.1UF" C0402#1 4350,2324.37 r90 top
C71 "CAP_NP_C0402_DISCRETE_4.7UF" C0402#1 4310,2324.37 r90 top
C72 "CAP_NP_C0402_DISCRETE_4.7UF" C0402#1 4260,2049.37 r270 bottom
C73 "CAP_NP_C0402_DISCRETE_4.7UF" C0402#1 4300,2049.37 r270 bottom
C74 "CAP_NP_C0402_DISCRETE_18PF" C0402#1 4195,2454.37 r90 bottom
C75 "CAP_NP_C0402_DISCRETE_18PF" C0402#1 4195,2374.37 r270 bottom
C76 "CAP_NP_C0402_DISCRETE_0.1UF" C0402#1 4830,2964.37 r180 top
C77 "CAP_NP_C0805_DISCRETE_1NF" C0805#2 4215,2914.37 r270 bottom
C78 "CAP_NP_C0402_DISCRETE_0.1UF" C0402#1 4595,2534.37 r90 bottom
C79 "CAP_NP_C0402_DISCRETE_4.7UF" C0402#1 4410,2224.37 r0 top
C80 "CAP_NP_C0402_DISCRETE_0.1UF" C0402#1 4390,2324.37 r90 top
C81 "CAP_NP_C0402_DISCRETE_0.1UF" C0402#1 4430,2324.37 r90 top
C82 "CAP_NP_C0402_DISCRETE_4.7UF" C0402#1 4410,2264.37 r0 top
C83 "CAP_NP_C0402_DISCRETE_0.1UF" C0402#1 4435,2634.37 r90 bottom
C84 "CAP_NP_C0402_DISCRETE_0.1UF" C0402#1 4350,2634.37 r90 bottom
C85 "CAP_NP_C0402_DISCRETE_0.1UF" C0402#1 4195,2539.37 r90 bottom
C86 "CAP_NP_C0402_DISCRETE_4.7UF" C0402#2 4115,2559.37 r0 bottom
C87 "CAP_NP_C0402_DISCRETE_4.7UF" C0402#1 4615,2614.37 r0 bottom
C88 "CAP_NP_C0402_DISCRETE_0.1UF" C0402#1 4285,2634.37 r90 bottom
C89 "CAP_NP_C0402_DISCRETE_0.1UF" C0402#1 4505,2634.37 r90 bottom
C90 "CAP_NP_C0402_DISCRETE_0.1UF" C0402#2 4615,2695 r0 bottom
C91 "CAP_NP_C0402_DISCRETE_10PF" C0402#1 4255.32,1149.37 r270 top
C92 "CAP_NP_C0402_DISCRETE_NC" C0402#1 4235.32,1209.37 r180 top
C93 "CAP_NP_C0402_DISCRETE_NC" C0402#1 4235.32,1089.37 r180 top
C94 "CAP_NP_C0402_DISCRETE_0.1UF" C0402#1 3790,1444.37 r0 bottom
C95 "CAP_NP_C0603_DISCRETE_10UF" C0603#1 3855,1654.37 r180 top
C96 "CAP_NP_C0402_DISCRETE_0.1UF" C0402#1 3855,1704.37 r180 top
C97 "CAP_NP_C0402_DISCRETE_0.1UF" C0402#1 3340,2959.37 r270 bottom
C98 "CAP_NP_C0402_DISCRETE_0.1UF" C0402#1 3380,2959.37 r270 bottom
C99 "CAP_NP_C0402_DISCRETE_0.1UF" C0402#1 3545,3604.37 r90 bottom
C100 "CAP_NP_C0402_DISCRETE_0.1UF" C0402#1 3315,3664.37 r0 bottom
C101 "CAP_NP_C0402_DISCRETE_10UF" C0402#1 3505,3604.37 r90 bottom
C102 "CAP_NP_C0402_DISCRETE_NC" C0402#1 3690,2374.37 r90 bottom
C103 "CAP_NP_C0402_DISCRETE_NC" C0402#1 3690,2454.37 r90 bottom
C104 "CAP_NP_C0402_DISCRETE_0.1UF" C0402#1 3840,3664.37 r0 bottom
C105 "CAP_NP_C0402_DISCRETE_10UF" C0402#1 4030,3604.37 r90 bottom
C106 "CAP_NP_C0402_DISCRETE_0.1UF" C0402#1 4070,3604.37 r90 bottom
C107 "CAP_NP_C0402_DISCRETE_0.1UF" C0402#1 3525,3664.37 r0 bottom
C108 "CAP_NP_C0402_DISCRETE_0.1UF" C0402#1 4050,3664.37 r0 bottom
C109 "CAP_NP_C0402_DISCRETE_0.1UF" C0402#1 3675,2819.37 r0 bottom
C110 "CAP_NP_C0402_DISCRETE_4.7UF" C0402#1 3675,2644.37 r0 bottom
C111 "CAP_NP_C0402_DISCRETE_0.1UF" C0402#1 3555,2614.37 r90 bottom
C112 "CAP_NP_C0402_DISCRETE_0.1UF" C0402#1 3675,2549.37 r0 bottom
C113 "CAP_NP_C0402_DISCRETE_0.22UF" C0402#1 2465,3129.37 r90 bottom
C114 "CAP_NP_C0402_DISCRETE_0.22UF" C0402#1 2555,3129.37 r90 bottom
C115 "CAP_NP_C0402_DISCRETE_0.22UF" C0402#1 2595,3129.37 r90 bottom
C116 "CAP_NP_C0402_DISCRETE_0.22UF" C0402#1 2505,3129.37 r90 bottom
C117 "CAP_NP_C0402_DISCRETE_0.22UF" C0402#1 2645,3129.37 r90 bottom
C118 "CAP_NP_C0402_DISCRETE_0.22UF" C0402#1 2685,3129.37 r90 bottom
C119 "CAP_NP_C0402_DISCRETE_0.22UF" C0402#1 2740,3129.37 r90 bottom
C120 "CAP_NP_C0402_DISCRETE_0.22UF" C0402#1 2780,3129.37 r90 bottom
C121 "CAP_NP_C0402_DISCRETE_1UF" C0402#1 2870,3159.37 r90 top
C122 "CAP_NP_C0402_DISCRETE_1UF" C0402#1 2910,3159.37 r90 top
C123 "CAP_NP_C0402_DISCRETE_100PF" C0402#2 2760,3239.37 r0 bottom
C124 "CAP_NP_C0603_DISCRETE_1UF" C0603#2 2870,3189.37 r0 bottom
C125 "CAP_NP_C0402_DISCRETE_0.1UF" C0402#1 4655,1994.37 r0 top
C126 "CAP_NP_C0603_DISCRETE_10UF" C0603#1 4745,2114.37 r270 top
C127 "CAP_NP_C0402_DISCRETE_0.1UF" C0402#1 4795,2114.37 r270 top
C128 "CAP_NP_C0402_DISCRETE_0.1UF" C0402#1 5155,3254.37 r90 top
C129 "CAP_NP_C0603_DISCRETE_10UF" C0603#1 5095,3169.37 r0 bottom
C130 "CAP_NP_C0402_DISCRETE_0.1UF" C0402#1 5095,3119.37 r0 bottom
C131 "CAP_NP_C0402_DISCRETE_0.1UF" C0402#1 4765,2034.37 r0 top
C132 "CAP_NP_C0402_DISCRETE_0.1UF" C0402#1 4765,2264.37 r0 top
C133 "CAP_NP_C0603_DISCRETE_10UF" C0603#1 5095,3379.37 r0 bottom
C134 "CAP_NP_C0603_DISCRETE_10UF" C0603#1 4745,2344.37 r270 top
C135 "CAP_NP_C0402_DISCRETE_0.1UF" C0402#1 4795,2344.37 r270 top
C136 "CAP_NP_C0603_DISCRETE_10UF" C0603#1 5095,3234.37 r0 bottom
C137 "CAP_NP_C0603_DISCRETE_10UF" C0603#1 5095,3439.37 r0 bottom
C138 "CAP_NP_C0402_DISCRETE_0.1UF" C0402#1 5095,3329.37 r0 bottom
C139 "CAP_NP_C0402_DISCRETE_0.1UF" C0402#1 5035,2119.37 r270 bottom
C140 "CAP_NP_C0603_DISCRETE_10UF" C0603#1 4995,2134.37 r90 top
C141 "CAP_NP_C0402_DISCRETE_0.1UF" C0402#1 4945,2134.37 r90 top
C142 "CAP_NP_C0402_DISCRETE_0.1UF" C0402#1 5035,1259.37 r270 bottom
C143 "CAP_NP_C0603_DISCRETE_10UF" C0603#1 4995,1264.37 r90 top
C144 "CAP_NP_C0402_DISCRETE_0.1UF" C0402#1 4945,1264.37 r90 top
C145 "CAP_NP_C0402_DISCRETE_0.1UF" C0402#1 3365,2974.37 r90 top
C146 "CAP_NP_C0402_DISCRETE_NC" C0402#1 3335,2859.37 r90 top
C147 "CAP_NP_C0603_DISCRETE_10UF" C0603#1 3120,3009.37 r270 top
C148 "CAP_NP_C0603_DISCRETE_10UF" C0603#1 3180,3009.37 r270 top
C149 "CAP_NP_C0402_DISCRETE_0.1UF" C0402#1 3275,3104.37 r0 top
C150 "CAP_NP_C0603_DISCRETE_22UF" C0603#1 3770,3009.37 r90 top
C151 "CAP_CASE-B_3528_220UF" CASE-B_3528 3680,3014.37 r90 top
C152 "CAP_NP_C0402_DISCRETE_0.1UF" C0402#1 3820,3009.37 r90 top
C153 "CAP_NP_C0402_DISCRETE_33PF" C0402#1 4545,1044.37 r90 bottom
C154 "CAP_NP_C0402_DISCRETE_33PF" C0402#1 4595,1044.37 r90 bottom
C155 "CAP_NP_C0402_DISCRETE_33PF" C0402#1 4495,1044.37 r90 bottom
C156 "CAP_NP_C0402_DISCRETE_0.1UF" C0402#1 3545,2534.37 r90 top
C157 "CAP_NP_C0402_DISCRETE_0.1UF" C0402#1 3505,2534.37 r90 top
C158 "CAP_NP_C0402_DISCRETE_0.1UF" C0402#2 4695,2554.37 r0 bottom
C159 "CAP_NP_C0402_DISCRETE_0.1UF" C0402#1 3770,2549.37 r0 bottom
C160 "CAP_NP_C0402_DISCRETE_4.7UF" C0402#1 4195,2634.37 r90 bottom
C161 "CAP_NP_C0402_DISCRETE_4.7UF" C0402#1 4000,2924.37 r0 bottom
C162 "CAP_NP_C0402_DISCRETE_4.7UF" C0402#2 2290,1884.37 r0 bottom
C163 "CAP_NP_C0402_DISCRETE_0.1UF" C0402#2 2290,1924.37 r0 bottom
C164 "CAP_NP_C0603_DISCRETE_10UF" C0603#1 2295,2014.37 r0 bottom
C165 "CAP_NP_C0402_DISCRETE_0.1UF" C0402#1 2295,2064.37 r0 bottom
C166 "CAP_NP_C0402_DISCRETE_0.1UF" C0402#1 1745,2409.37 r90 bottom
C167 "CAP_NP_C0402_DISCRETE_4.7UF" C0402#1 1705,2409.37 r90 bottom
C168 "CAP_NP_C0402_DISCRETE_0.1UF" C0402#1 1745,2329.37 r270 bottom
C169 "CAP_NP_C0402_DISCRETE_4.7UF" C0402#1 1705,2329.37 r270 bottom
C170 "CAP_NP_C0402_DISCRETE_4.7UF" C0402#1 1485,2134.37 r90 bottom
C171 "CAP_NP_C0402_DISCRETE_0.1UF" C0402#1 1525,2134.37 r90 bottom
C172 "CAP_NP_C0603_DISCRETE_10UF" C0603#1 1615,2134.37 r270 bottom
C173 "CAP_NP_C0402_DISCRETE_0.1UF" C0402#1 1665,2134.37 r270 bottom
C174 "CAP_NP_C0402_DISCRETE_1UF" C0402#1 2155,2199.37 r0 bottom
C175 "CAP_NP_C0402_DISCRETE_0.1UF" C0402#1 2155,2239.37 r0 bottom
C176 "CAP_NP_C0402_DISCRETE_1UF" C0402#1 1865,2609.37 r90 bottom
C177 "CAP_NP_C0402_DISCRETE_1UF" C0402#1 1825,2609.37 r90 bottom
C178 "CAP_NP_C0402_DISCRETE_1UF" C0402#1 1785,2609.37 r90 bottom
C179 "CAP_NP_C0402_DISCRETE_1UF" C0402#1 1745,2609.37 r90 bottom
C180 "CAP_NP_C0402_DISCRETE_10UF" C0402#2 1725,2509.37 r0 bottom
C181 "CAP_NP_C0402_DISCRETE_10UF" C0402#2 1725,2469.37 r0 bottom
C182 "CAP_NP_C0402_DISCRETE_10UF" C0402#1 1935,2219.37 r270 bottom
C183 "CAP_NP_C0402_DISCRETE_4.7UF" C0402#1 2200,3009.37 r90 top
C184 "CAP_NP_C0402_DISCRETE_100PF" C0402#1 2300,3069.37 r0 top
C185 "CAP_NP_C0402_DISCRETE_0.22UF" C0402#2 1225,2734.37 r0 bottom
C186 "CAP_NP_C0402_DISCRETE_1UF" C0402#1 1855,3449.37 r270 bottom
C187 "CAP_NP_C0402_DISCRETE_0.1UF" C0402#1 2065,2609.37 r270 bottom
C188 "CAP_NP_C0402_DISCRETE_1UF" C0402#2 2005,2724.37 r0 bottom
C189 "CAP_NP_C0603_DISCRETE_22UF" C0603#1 1000,2939.37 r90 bottom
C190 "CAP_NP_C0402_DISCRETE_0.1UF" C0402#1 1050,2939.37 r90 bottom
C191 "CAP_NP_C0805_DISCRETE_47UF" C0805#2 1640,2799.37 r0 bottom
C192 "CAP_NP_C0402_DISCRETE_1UF" C0402#1 1395,2889.37 r270 bottom
C193 "CAP_NP_C0805_DISCRETE_47UF" C0805#1 1490,2799.37 r0 bottom
C194 "CAP_NP_C0603_DISCRETE_100PF" C0603#2 1960,2814.37 r0 bottom
C195 "CAP_NP_C0402_DISCRETE_0.1UF" C0402#1 1760,3009.37 r270 bottom
C196 "CAP_NP_C0603_DISCRETE_10UF" C0603#1 1155,3349.37 r270 bottom
C197 "CAP_NP_C0402_DISCRETE_0.1UF" C0402#1 1170,3319.37 r270 top
C198 "CAP_NP_C0402_DISCRETE_0.1UF" C0402#1 1130,3319.37 r270 top
C199 "CAP_NP_C0402_DISCRETE_0.1UF" C0402#1 980,3319.37 r270 top
C200 "CAP_NP_C0402_DISCRETE_0.1UF" C0402#1 940,3319.37 r270 top
C201 "CAP_NP_C0402_DISCRETE_0.1UF" C0402#1 1260,3329.37 r270 bottom
C202 "CAP_NP_C0402_DISCRETE_0.1UF" C0402#1 1300,3329.37 r270 bottom
C203 "CAP_NP_C0603_DISCRETE_10UF" C0603#1 855,3349.37 r270 bottom
C204 "CAP_NP_C0603_DISCRETE_10UF" C0603#1 915,2614.37 r0 bottom
C205 "CAP_NP_C0402_DISCRETE_0.1UF" C0402#1 915,2564.37 r0 bottom
C206 "CAP_NP_C0402_DISCRETE_0.1UF" C0402#1 1025,2439.37 r270 bottom
C207 "CAP_NP_C0603_DISCRETE_10UF" C0603#1 1095,3349.37 r270 bottom
C209 "CAP_NP_C0402_DISCRETE_220PF" C0402#1 1025,2519.37 r90 bottom
C210 "CAP_NP_C0402_DISCRETE_220PF" C0402#2 790,2499.37 r0 bottom
C211 "CAP_NP_C0402_DISCRETE_1UF" C0402#1 1005,2309.37 r90 bottom
C212 "CAP_NP_C0402_DISCRETE_10NF" C0402#1 205,1310 r90 bottom
CN1 "WIFI_ANT_UFL-3_WIFI-ANT" UFL-3 4255,1001.37 r180 top
D1 "DIODE BI-DIR TRIG_SMA_CA_SMAJ13CA" SMA_CA 530,3154.37 r270 top
D2 "DIODE_SOD-123_1N4148W" SOD-123#1 915,2939.37 r90 bottom
D3 "LED_LED0603_GREEN" LED0603 475,389.37 r90 top
D4 "LED_LED0603_GREEN" LED0603 575,389.37 r90 top
D5 "BAT54C_SOT23_BAT54C" SOT23#1 405,3074.37 r270 bottom
D6 "DIODE BI-DIR TRIG_ES0402_KLXES15AAA1" ES0402#1 540,3074.37 r270 bottom
D7 "DIODE BI-DIR TRIG_SMB-CA_SMBJ15CA" SMB-CA 1695,1134.37 r270 bottom
D8 "DIODE BI-DIR TRIG_SMB-CA_SMBJ15CA" SMB-CA 1390,1134.37 r270 bottom
D9 "DIODE BI-DIR TRIG_SMB-CA_SMBJ15CA" SMB-CA 1845,1134.37 r270 bottom
D10 "DIODE BI-DIR TRIG_SMB-CA_SMBJ15CA" SMB-CA 1540,1134.37 r270 bottom
D11 "DIODE BI-DIR TRIG_ES0402_KLXES15AAA1" ES0402#1 4480,719.37 r270 top
D12 "DIODE BI-DIR TRIG_ES0402_KLXES15AAA1" ES0402#1 4430,719.37 r270 top
D13 "DIODE BI-DIR TRIG_ES0402_KLXES15AAA1" ES0402#1 4380,719.37 r270 top
D14 "DIODE BI-DIR TRIG_ES0402_KLXES15AAA1" ES0402#1 4240,719.37 r270 top
D15 "DIODE BI-DIR TRIG_ES0402_KLXES15AAA1" ES0402#1 4190,719.37 r270 top
D16 "DIODE BI-DIR TRIG_ES0402_KLXES15AAA1" ES0402#1 4140,719.37 r270 top
D17 "DIODE BI-DIR TRIG_ES0402_KLXES15AAA1" ES0402#1 4090,719.37 r270 top
D18 "DIODE BI-DIR TRIG_SMB-CA_SMBJ6.5CA" SMB-CA 3475,1134.37 r270 bottom
D19 "DIODE_SCHTKY_SOD523_IC_RB521S-30" SOD523 3685,1534.37 r90 bottom
D20 "DIODE BI-DIR TRIG_SMB-CA_SMBJ6.5CA" SMB-CA 3635,1134.37 r270 bottom
D21 "DIODE BI-DIR TRIG_SMB-CA_SMBJ6.5CA" SMB-CA 3165,1134.37 r270 bottom
D22 "DIODE BI-DIR TRIG_SMB-CA_SMBJ6.5CA" SMB-CA 3325,1134.37 r270 bottom
D23 "DIODE_SCHTKY_SOD523_IC_RB521S-30" SOD523 3375,1534.37 r90 bottom
D24 "DIODE BI-DIR TRIG_SMB-CA_SMBJ6.5CA" SMB-CA 2795,1134.37 r270 bottom
D25 "DIODE BI-DIR TRIG_SMB-CA_SMBJ6.5CA" SMB-CA 2955,1134.37 r270 bottom
D26 "DIODE BI-DIR TRIG_SMB-CA_SMBJ6.5CA" SMB-CA 2475,1134.37 r270 bottom
D27 "DIODE BI-DIR TRIG_SMB-CA_SMBJ6.5CA" SMB-CA 2635,1134.37 r270 bottom
D28 "DIODE_SCHTKY_SOD-123_IC_1N5819W" SOD-123#2 2970,3119.37 r0 bottom
D29 "DIODE BI-DIR TRIG_ES0402_KLXES15AAA1" ES0402#1 2930,3259.37 r180 top
D30 "DIODE BI-DIR TRIG_ES0402_KLXES15AAA1" ES0402#1 2760,3409.37 r0 bottom
D31 "DIODE BI-DIR TRIG_ES0402_KLXES15AAA1" ES0402#2 2510,3409.37 r0 bottom
D32 "DIODE BI-DIR TRIG_ES0402_KLXES15AAA1" ES0402#1 2850,3259.37 r0 top
D33 "DIODE BI-DIR TRIG_ES0402_KLXES15AAA1" ES0402#1 2510,3464.37 r0 bottom
D34 "DIODE BI-DIR TRIG_ES0402_KLXES15AAA1" ES0402#1 2870,3239.37 r0 bottom
D35 "DIODE BI-DIR TRIG_ES0402_KLXES15AAA1" ES0402#1 1370,3419.37 r270 top
D36 "DIODE BI-DIR TRIG_ES0402_KLXES15AAA1" ES0402#1 1310,3419.37 r270 top
F1 "FUSE_F1812_SMD1812P200TF16" F1812 395,3149.37 r270 top
H1 "SPACER_NPTH_M3_IC_NPTH_M3" NPTH_M3 157.48,3622.04 r0 top
H2 "SPACER_NPTH_M3_IC_NPTH_M3" NPTH_M3 157.48,196.85 r0 top
H3 "SPACER_NPTH_M3_IC_NPTH_M3" NPTH_M3 5078.73,196.85 r0 top
H4 "SPACER_NPTH_M3_IC_NPTH_M3" NPTH_M3 5078.73,3622.04 r0 top
J1 "DC-044A-20A_DC_IN_TH_3P_10R1X11R6_DC-044A-20A" DC_IN_TH_3P_10R1X11R6 548.26,3585.57 r270 top
J2 "1X2PIN_ZH1P5MM_TH_2P_A1501WV-2P" ZH1P5MM_TH_2P 944.53,3117.3 r0 top
J3 "DF40C-100DP_DF40C-100DP-0P4V_DF40C-100DP-0.4V(51)" DF40C-100DP-0P4V 1319.38,774.42 r0 top
J4 "SGDBM-05-100P-H10_DF40HC-100DS-0P4V_DF40C-100DS-0.4V(51)" DF40HC-100DS-0P4V 1319.38,2610.44 r0 top
J5 "DF40C-100DP_DF40C-100DP-0P4V_DF40C-100DP-0.4V(51)" DF40C-100DP-0P4V 2325.98,774.42 r0 top
J6 "SGDBM-05-100P-H10_DF40HC-100DS-0P4V_DF40C-100DS-0.4V(51)" DF40HC-100DS-0P4V 2325.98,2610.44 r0 top
J7 "1X4PIN_XH2R54-4P-V_XH-4A" XH2R54-4P-V 984.25,157.79 r0 top
J8 "1X2PIN_GH1P25_TH_2P_1.25T-2A" GH1P25_TH_2P 681.69,3112.39 r0 top
J9 "CON6_DB2ERC-3P81-6P_CON6" DB2ERC-3P81-6P 1850.39,100.39 r180 top
J10 "TF_CARD_TFCARD_IO_TF_CARD" TFCARD 4372.04,321.06 r0 top
J11 "1X2PIN_HDR1X2-2R54-TM-VM_HDR1X2-2R54-TM-VM" HDR1X2-2R54-TM-VM 3737.67,538.19 r0 top
J12 "CON4_DB2ERC-3P81-4P_WJ15EDGRC-3.81-4P" DB2ERC-3P81-4P 3582.28,100.39 r180 top
J13 "1X2PIN_HDR1X2-2R54-TM-VM_HDR1X2-2R54-TM-VM" HDR1X2-2R54-TM-VM 3432.67,538.19 r0 top
J14 "CON4_DB2ERC-3P81-4P_WJ15EDGRC-3.81-4P" DB2ERC-3P81-4P 2794.88,100.39 r180 top
J15 "HY911130A_HY911130A_HY911130A" HY911130A 4606.29,3425.19 r0 top
J16 "USB3D0_USB2D0-A-D_USB3D0-AF-18P_USB3D0_USB2D0-A-D" USB3D0-AF-18P 3421.89,3515.01 r180 top
J17 "USB_AF_USB-AF_USB_AF" USB-AF 4015.74,3468.5 r0 top
J18 "A111926-A-05-R_CON_RA_HDMI_19P_0P5_SM_IO_A111926-A-05-R" CON_RA_HDMI_19P_0P5_SM 2637.79,3596.91 r180 top
J19 "FPC-30P_FPC-30P-0P5_FPC_0R5_30P_D" FPC-30P-0P5 5088.2,2637.59 r270 bottom
J20 "FPC-30P_FPC-30P-0P5_FPC_0R5_30P_D" FPC-30P-0P5 5088.2,2637.59 r90 top
J21 "FPC-24P_FPC_24P_0P5_FPC_0P5_24P_D" FPC_24P_0P5 5084.95,1692.91 r90 bottom
J22 "FPC-24P_FPC_24P_0P5_FPC_0P5_24P_D" FPC_24P_0P5 5084.95,1692.91 r270 top
J23 "FPC-24P_FPC_24P_0P5_FPC_0P5_24P_D" FPC_24P_0P5 5084.95,826.77 r90 bottom
J24 "FPC-24P_FPC_24P_0P5_FPC_0P5_24P_D" FPC_24P_0P5 5084.95,826.77 r270 top
J25 "MINI-PCIE_PCIE_52P_MINI-PCIE" PCIE_52P 4244.24,2677.16 r180 top
J26 "MIC_JACK_EAR_JACK_PJ-325C5-G" EAR_JACK 1572.67,3420.58 r270 top
J27 "MIC_JACK_EAR_JACK_PJ-325C5-R" EAR_JACK 2005.74,3420.58 r270 top
J28 "1X2PIN_PH-1X2-2P0_L_PH-2A" PH-1X2-2P0_L 1225.47,3124.62 r180 top
J29 "1X2PIN_HDR1X2-2R54-TM-VM_HDR1X2-2R54-TM-VM" HDR1X2-2R54-TM-VM 2005,3009.37 r180 top
J30 "TYPE-C-24P_USB-C-SMD_TYC-324G_TYPE-C" USB-C-SMD_TYC-324G 1102.36,3651.17 r180 top
J31 "SIM-7-1_NANO_SIM_SIM-7-1" NANO_SIM 4370.07,326.96 r0 bottom
L1 "IND_L4520_DISCRETE_3.3UH" L4520 185,1564.37 r270 top
L2 "IND_L0518_DISCRETE_1.5UH" L0518 190,2274.37 r270 top
L3 "IND_L2520_DISCRETE_2.2UH" L2520 4280,2164.37 r270 bottom
L5 "BEAD_L0603_DISCRETE_330R 100MHZ" L0603#1 3120,3654.37 r0 bottom
L6 "IND_L4520_DISCRETE_3.3UH" L4520 3505,3009.37 r0 top
L7 "BEAD_L0603_DISCRETE_330R 100MHZ" L0603#2 1105,3714.37 r0 bottom
LED1 "LED_LED0603_RED" LED0603 375,389.37 r90 top
P1 "MIC_POM_MIC2-4R00-TM_IC_MIC_POM" MIC2-4R00-TM 2300,3199.37 r0 top
Q1 "MOSFET_P_SOT23_IC_AO3407" SOT23#2 410,2304.37 r0 bottom
Q2 "NPN_SOT23_IC_SS8050" SOT23#2 535,2304.37 r0 bottom
Q3 "NPN_SOT23_IC_SS8050" SOT23#2 340,379.37 r0 bottom
Q4 "NPN_SOT23_IC_SS8050" SOT23#2 470,379.37 r0 bottom
Q5 "NPN_SOT23_IC_SS8050" SOT23#2 600,379.37 r0 bottom
Q6 "MOSFET_P_SOT23_IC_AO3407" SOT23#2 3790,1534.37 r0 bottom
Q7 "2SK3018_SOT23_IC_2SK3018" SOT23#2 2510,3324.37 r0 bottom
Q8 "2SK3018_SOT23_IC_2SK3018" SOT23#2 2760,3324.37 r0 bottom
Q9 "2SK3018_SOT23_IC_2SK3018" SOT23#2 2510,3554.37 r0 bottom
Q10 "2SK3018_SOT23_IC_2SK3018" SOT23#2 2760,3554.37 r0 bottom
Q11 "2SK3018_SOT23_IC_2SK3018" SOT23#2 2635,3554.37 r0 bottom
Q12 "2SK3018_SOT23_IC_2SK3018" SOT23#1 2840,3014.37 r0 top
Q13 "2SK3018_SOT23_IC_2SK3018" SOT23#1 2465,3014.37 r0 top
Q14 "2SK3018_SOT23_IC_2SK3018" SOT23#1 2590,3014.37 r0 top
Q15 "2SK3018_SOT23_IC_2SK3018" SOT23#1 2715,3014.37 r0 top
Q16 "MOSFET N_SOT23_WNM2016-3/TR" SOT23#1 1640,3009.37 r0 bottom
Q17 "MOSFET N_SOT23_WNM2016-3/TR" SOT23#1 1490,3009.37 r0 bottom
R1 "RES_R0603_DISCRETE_0R" R0603#1 825,1449.37 r0 bottom
R2 "RES_R0603_DISCRETE_NC" R0603#1 825,1389.37 r0 bottom
R3 "RES_R0402_DISCRETE_1K" R0402#1 985,1249.37 r0 bottom
R4 "RES_R0402_DISCRETE_3.4K" R0402#1 985,1329.37 r0 bottom
R5 "RES_R0402_DISCRETE_6.8K" R0402#1 985,1524.37 r0 bottom
R6 "RES_R0402_DISCRETE_100K" R0402#2 175,1829.37 r90 bottom
R7 "RES_R0402_DISCRETE_30K" R0402#2 135,1829.37 r270 bottom
R8 "RES_R0402_DISCRETE_140K" R0402#2 215,1909.37 r270 bottom
R9 "RES_R0402_DISCRETE_20K" R0402#2 175,1909.37 r90 bottom
R10 "RES_R0603_DISCRETE_NC" R0603#1 445,2089.37 r90 bottom
R11 "RES_R0603_DISCRETE_0R" R0603#1 375,2089.37 r90 bottom
R12 "RES_R0402_DISCRETE_20K" R0402#2 410,2219.37 r0 bottom
R13 "RES_R0402_DISCRETE_1K" R0402#2 530,2179.37 r0 bottom
R14 "RES_R0402_DISCRETE_3.3R" R0402#2 330,2434.37 r270 top
R15 "RES_R0402_DISCRETE_140K" R0402#2 295,2619.37 r0 bottom
R16 "RES_R0402_DISCRETE_10K" R0402#1 530,2219.37 r0 bottom
R17 "RES_R0402_DISCRETE_20K" R0402#2 295,2579.37 r0 bottom
R18 "RES_R0402_DISCRETE_75K" R0402#2 315,2424.37 r90 bottom
R19 "RES_R0402_DISCRETE_100K" R0402#1 165,2484.37 r0 bottom
R20 "RES_R0402_DISCRETE_10K" R0402#2 275,2424.37 r270 bottom
R21 "RES_R0402_DISCRETE_100K" R0402#1 165,2444.37 r0 bottom
R22 "RES_R0402_DISCRETE_NC" R0402#1 165,2404.37 r0 bottom
R23 "RES_R0402_DISCRETE_25.5K" R0402#2 1325,2674.37 r90 bottom
R24 "RES_R0402_DISCRETE_10K" R0402#2 1345,2734.37 r0 bottom
R25 "RES_R0402_DISCRETE_10K" R0402#2 770,394.37 r270 bottom
R26 "RES_R0402_DISCRETE_560R" R0402#1 835,314.37 r0 bottom
R27 "RES_R0402_DISCRETE_560R" R0402#2 1135,314.37 r0 bottom
R28 "RES_R0402_DISCRETE_100R" R0402#2 245,839.37 r270 bottom
R29 "RES_R0402_DISCRETE_10K" R0402#2 985,394.37 r270 bottom
R30 "RES_R0402_DISCRETE_10K" R0402#2 245,1014.37 r270 bottom
R31 "RES_R0402_DISCRETE_100R" R0402#2 245,1095 r90 bottom
R32 "RES_R0402_DISCRETE_10K" R0402#2 265,1205 r0 bottom
R33 "RES_R0402_DISCRETE_100R" R0402#2 265,1165 r0 bottom
R34 "RES_R0402_DISCRETE_4.7K" R0402#2 375,274.37 r90 top
R35 "RES_R0402_DISCRETE_10K" R0402#2 475,274.37 r90 top
R36 "RES_R0402_DISCRETE_10K" R0402#2 575,274.37 r90 top
R37 "RES_R0402_DISCRETE_4.7K" R0402#2 340,514.37 r0 bottom
R38 "RES_R0402_DISCRETE_1K" R0402#2 470,514.37 r0 bottom
R39 "RES_R0402_DISCRETE_1K" R0402#2 600,514.37 r0 bottom
R40 "RES_R0402_DISCRETE_10K" R0402#1 340,474.37 r0 bottom
R41 "RES_R0402_DISCRETE_10K" R0402#1 470,474.37 r0 bottom
R42 "RES_R0402_DISCRETE_10K" R0402#1 600,474.37 r0 bottom
R43 "RES_R0402_DISCRETE_10K" R0402#2 495,179.37 r270 bottom
R44 "RES_R0402_DISCRETE_22R" R0402#2 375,179.37 r270 bottom
R45 "RES_R0402_DISCRETE_22R" R0402#2 535,179.37 r270 bottom
R46 "RES_R0402_DISCRETE_10K" R0402#2 135,2959.37 r90 bottom
R47 "RES_R0402_DISCRETE_10K" R0402#2 175,2959.37 r90 bottom
R48 "RES_R0402_DISCRETE_22R" R0402#2 215,2959.37 r270 bottom
R49 "RES_R0603_DISCRETE_0R" R0603#1 1735,519.37 r270 bottom
R50 "RES_R0603_DISCRETE_0R" R0603#1 1805,519.37 r270 bottom
R51 "RES_R0603_DISCRETE_0R" R0603#1 1435,524.37 r270 bottom
R52 "RES_R0603_DISCRETE_0R" R0603#1 1500,524.37 r270 bottom
R53 "RES_R0402_DISCRETE_22R" R0402#2 4480,819.37 r270 top
R54 "RES_R0402_DISCRETE_22R" R0402#2 4430,819.37 r270 top
R55 "RES_R0402_DISCRETE_22R" R0402#2 4380,819.37 r270 top
R56 "RES_R0402_DISCRETE_0R" R0402#2 4330,819.37 r270 top
R57 "RES_R0402_DISCRETE_22R" R0402#2 4240,819.37 r270 top
R58 "RES_R0402_DISCRETE_22R" R0402#2 4190,819.37 r270 top
R59 "RES_R0402_DISCRETE_22R" R0402#2 4140,819.37 r270 top
R60 "RES_R0402_DISCRETE_100R" R0402#2 4090,819.37 r270 top
R61 "RES_R0402_DISCRETE_10K" R0402#2 4045,819.37 r90 top
R62 "RES_R0402_DISCRETE_4.7K" R0402#1 3595,1344.37 r0 bottom
R63 "RES_R0603_DISCRETE_120R" R0603#1 3765,449.37 r0 top
R64 "RES_R0402_DISCRETE_4.7K" R0402#1 3510,1344.37 r0 bottom
R65 "RES_R0402_DISCRETE_10K" R0402#1 3555,1709.37 r0 bottom
R66 "RES_R0603_DISCRETE_0R" R0603#1 3765,389.37 r0 top
R67 "RES_R0603_DISCRETE_0R" R0603#1 3675,419.37 r270 top
R68 "RES_R0603_DISCRETE_0R" R0603#1 3465,389.37 r0 top
R69 "RES_R0603_DISCRETE_0R" R0603#1 3375,419.37 r270 top
R70 "RES_R0402_DISCRETE_4.7K" R0402#1 3285,1344.37 r0 bottom
R71 "RES_R0603_DISCRETE_120R" R0603#1 3465,449.37 r0 top
R72 "RES_R0402_DISCRETE_4.7K" R0402#1 3200,1344.37 r0 bottom
R73 "RES_R0402_DISCRETE_10K" R0402#1 3245,1709.37 r0 bottom
R74 "RES_R0603_DISCRETE_0R" R0603#1 2780,509.37 r270 bottom
R75 "RES_R0603_DISCRETE_0R" R0603#1 2835,509.37 r270 bottom
R76 "RES_R0603_DISCRETE_0R" R0603#1 2530,509.37 r270 bottom
R77 "RES_R0603_DISCRETE_0R" R0603#1 2585,509.37 r270 bottom
R78 "RES_R0603_DISCRETE_120R" R0603#1 2875,1344.37 r0 bottom
R79 "RES_R0603_DISCRETE_120R" R0603#1 2555,1344.37 r0 bottom
R80 "RES_R0402_DISCRETE_4.7K" R0402#2 4455,2084.37 r90 bottom
R81 "RES_R0402_DISCRETE_4.7K" R0402#2 4500,2084.37 r90 bottom
R82 "RES_R0402_DISCRETE_4.7K" R0402#2 4590,2084.37 r90 bottom
R83 "RES_R0402_DISCRETE_4.7K" R0402#2 4365,2084.37 r270 bottom
R84 "RES_R0402_DISCRETE_22R" R0402#2 4455,2189.37 r90 bottom
R85 "RES_R0402_DISCRETE_22R" R0402#2 4500,2189.37 r90 bottom
R86 "RES_R0402_DISCRETE_2.49K" R0402#2 4245,2634.37 r90 bottom
R87 "RES_R0402_DISCRETE_22R" R0402#2 4545,2189.37 r90 bottom
R88 "RES_R0402_DISCRETE_22R" R0402#2 4590,2189.37 r90 bottom
R89 "RES_R0402_DISCRETE_22R" R0402#2 4365,2189.37 r90 bottom
R90 "RES_R0402_DISCRETE_22R" R0402#2 4410,2189.37 r90 bottom
R91 "RES_R0402_DISCRETE_4.7K" R0402#2 4545,2084.37 r270 bottom
R92 "RES_R0402_DISCRETE_4.7K" R0402#2 4410,2084.37 r270 bottom
R93 "RES_R0402_DISCRETE_4.7K" R0402#1 4615,2469.37 r0 bottom
R94 "RES_R0402_DISCRETE_4.7K" R0402#1 4615,2429.37 r0 bottom
R95 "RES_R0402_DISCRETE_4.7K" R0402#2 4175,2154.37 r0 bottom
R96 "RES_R0402_DISCRETE_NC" R0402#2 4095,2154.37 r0 bottom
R97 "RES_R0402_DISCRETE_0R" R0402#2 4175,2304.37 r0 bottom
R98 "RES_R0402_DISCRETE_NC" R0402#1 4095,2304.37 r0 bottom
R99 "RES_R0402_DISCRETE_510R" R0402#2 4585,3639.37 r90 bottom
R100 "RES_R0402_DISCRETE_510R" R0402#2 4625,3639.37 r90 bottom
R101 "RES_R0805_DISCRETE_1M" R0805 4110,2914.37 r270 bottom
R102 "RES_R0402_DISCRETE_4.7K" R0402#1 4095,2254.37 r0 bottom
R103 "RES_R0402_DISCRETE_4.7K" R0402#1 4095,2209.37 r0 bottom
R104 "RES_R0402_DISCRETE_4.7K" R0402#1 4175,2209.37 r0 bottom
R105 "RES_R0402_DISCRETE_4.7K" R0402#2 4635,2534.37 r270 bottom
R106 "RES_R0402_DISCRETE_0R" R0402#2 4410,2184.37 r0 top
R107 "RES_R0402_DISCRETE_0R" R0402#2 4115,2519.37 r0 bottom
R108 "RES_R0402_DISCRETE_2.2R" R0402#2 3855,1504.37 r0 top
R109 "RES_R0402_DISCRETE_2.2R" R0402#2 3855,1544.37 r0 top
R110 "RES_R0402_DISCRETE_10K" R0402#2 3790,1404.37 r0 bottom
R111 "RES_R0402_DISCRETE_560R" R0402#2 3735,1709.37 r0 bottom
R112 "RES_R0402_DISCRETE_2.2R" R0402#2 3440,2959.37 r270 bottom
R113 "RES_R0402_DISCRETE_2.2R" R0402#2 3480,2959.37 r270 bottom
R114 "RES_R0402_DISCRETE_2.2R" R0402#1 3710,2249.37 r0 bottom
R115 "RES_R0402_DISCRETE_2.2R" R0402#1 3710,2209.37 r0 bottom
R116 "RES_R0402_DISCRETE_2.2R" R0402#2 3520,2959.37 r270 bottom
R117 "RES_R0402_DISCRETE_2.2R" R0402#2 3560,2959.37 r270 bottom
R118 "RES_R0402_DISCRETE_1K" R0402#2 3295,3604.37 r90 bottom
R119 "RES_R0402_DISCRETE_2.2R" R0402#2 3365,2494.37 r90 bottom
R120 "RES_R0402_DISCRETE_2.2R" R0402#2 3325,2494.37 r90 bottom
R121 "RES_R0402_DISCRETE_3.4K" R0402#2 3335,3604.37 r90 bottom
R122 "RES_R0402_DISCRETE_100K" R0402#1 3495,2634.37 r0 bottom
R123 "RES_R0402_DISCRETE_100K" R0402#1 3495,2594.37 r0 bottom
R124 "RES_R0402_DISCRETE_1K" R0402#2 3820,3604.37 r90 bottom
R125 "RES_R0402_DISCRETE_3.4K" R0402#2 3860,3604.37 r90 bottom
R126 "RES_R0603_DISCRETE_0R" R0603#1 3675,2734.37 r270 bottom
R127 "RES_R0402_DISCRETE_10K" R0402#1 2510,3239.37 r0 bottom
R128 "RES_R0402_DISCRETE_2.2K" R0402#2 2595,3319.37 r90 bottom
R129 "RES_R0402_DISCRETE_10K" R0402#2 2635,3239.37 r0 bottom
R130 "RES_R0402_DISCRETE_1K" R0402#2 2675,3319.37 r90 bottom
R131 "RES_R0402_DISCRETE_2.2K" R0402#2 2635,3319.37 r90 bottom
R132 "RES_R0402_DISCRETE_27K" R0402#1 2510,3644.37 r0 bottom
R133 "RES_R0402_DISCRETE_47K" R0402#2 2760,3644.37 r0 bottom
R134 "RES_R0402_DISCRETE_499R" R0402#2 2645,3129.37 r270 top
R135 "RES_R0402_DISCRETE_47K" R0402#1 2635,3644.37 r0 bottom
R136 "RES_R0402_DISCRETE_499R" R0402#2 2685,3129.37 r270 top
R137 "RES_R0402_DISCRETE_499R" R0402#2 2555,3129.37 r270 top
R138 "RES_R0402_DISCRETE_499R" R0402#2 2595,3129.37 r270 top
R139 "RES_R0402_DISCRETE_1.2K" R0402#2 2930,3219.37 r180 top
R140 "RES_R0402_DISCRETE_499R" R0402#2 2465,3129.37 r270 top
R141 "RES_R0402_DISCRETE_499R" R0402#2 2505,3129.37 r270 top
R142 "RES_R0402_DISCRETE_47K" R0402#1 2635,3464.37 r0 bottom
R143 "RES_R0402_DISCRETE_499R" R0402#2 2740,3129.37 r270 top
R144 "RES_R0402_DISCRETE_499R" R0402#2 2780,3129.37 r270 top
R145 "RES_R0402_DISCRETE_1K" R0402#2 2965,3009.37 r90 top
R146 "RES_R0402_DISCRETE_10K" R0402#2 2925,3009.37 r270 top
R147 "RES_R0402_DISCRETE_10K" R0402#2 4845,2734.37 r0 bottom
R148 "RES_R0402_DISCRETE_10K" R0402#2 4845,2814.37 r0 bottom
R149 "RES_R0402_DISCRETE_10K" R0402#2 4845,2559.37 r0 bottom
R150 "RES_R0402_DISCRETE_10K" R0402#2 4845,2479.37 r0 bottom
R151 "RES_R0402_DISCRETE_10K" R0402#2 4845,2694.37 r0 bottom
R152 "RES_R0402_DISCRETE_10K" R0402#2 4845,2774.37 r0 bottom
R153 "RES_R0402_DISCRETE_10K" R0402#2 4845,2599.37 r0 bottom
R154 "RES_R0402_DISCRETE_10K" R0402#2 4845,2519.37 r0 bottom
R155 "RES_R0402_DISCRETE_1K" R0402#2 4655,1954.37 r180 top
R156 "RES_R0402_DISCRETE_1K" R0402#2 5155,3164.37 r90 top
R157 "RES_R0402_DISCRETE_6.8K" R0402#2 4650,2194.37 r0 top
R158 "RES_R0402_DISCRETE_6.8K" R0402#2 5075,3094.37 r180 top
R159 "RES_R0402_DISCRETE_6.8K" R0402#2 5155,3399.37 r90 top
R160 "RES_R0402_DISCRETE_6.8K" R0402#2 4650,2424.37 r0 top
R161 "RES_R0402_DISCRETE_10K" R0402#2 4920,479.37 r90 bottom
R162 "RES_R0402_DISCRETE_10K" R0402#2 4920,479.37 r90 top
R163 "RES_R0402_DISCRETE_10K" R0402#2 4875,479.37 r90 bottom
R164 "RES_R0402_DISCRETE_10K" R0402#2 4875,479.37 r90 top
R165 "RES_R0402_DISCRETE_1K" R0402#2 4995,2119.37 r90 bottom
R166 "RES_R0402_DISCRETE_3.4K" R0402#2 5115,2119.37 r90 bottom
R167 "RES_R0402_DISCRETE_1K" R0402#2 4995,1259.37 r90 bottom
R168 "RES_R0402_DISCRETE_3.4K" R0402#2 5175,1264.37 r90 top
R169 "RES_R0402_DISCRETE_15K" R0402#2 4545,1144.37 r270 bottom
R170 "RES_R0402_DISCRETE_0R" R0402#2 4455,1044.37 r270 bottom
R171 "RES_R0402_DISCRETE_0R" R0402#2 4595,1144.37 r270 bottom
R172 "RES_R0402_DISCRETE_100K" R0402#2 3295,2859.37 r90 top
R173 "RES_R0402_DISCRETE_0R" R0402#2 4495,1144.37 r270 bottom
R174 "RES_R0402_DISCRETE_30K" R0402#2 3255,2859.37 r270 top
R175 "RES_R0402_DISCRETE_1K" R0402#2 3220,2979.37 r0 bottom
R176 "RES_R0402_DISCRETE_10K" R0402#1 3220,2939.37 r0 bottom
R177 "RES_R0402_DISCRETE_4.7K" R0402#2 4700,2809.37 r0 bottom
R178 "RES_R0402_DISCRETE_22R" R0402#2 4700,2849.37 r0 bottom
R179 "RES_R0402_DISCRETE_22R" R0402#2 4615,2849.37 r0 bottom
R180 "RES_R0402_DISCRETE_100R" R0402#2 4130,2384.37 r180 top
R181 "RES_R0402_DISCRETE_100R" R0402#2 4130,2424.37 r180 top
R182 "RES_R0402_DISCRETE_2.2R" R0402#2 3965,2384.37 r180 top
R183 "RES_R0402_DISCRETE_2.2R" R0402#2 3965,2424.37 r180 top
R184 "RES_R0402_DISCRETE_0R" R0402#1 2290,1964.37 r0 bottom
R185 "RES_R0402_DISCRETE_10K" R0402#1 2155,2364.37 r0 bottom
R186 "RES_R0402_DISCRETE_4.7R" R0402#2 1665,2409.37 r270 bottom
R187 "RES_R0402_DISCRETE_0R" R0402#2 1665,2329.37 r90 bottom
R188 "RES_R0402_DISCRETE_10K" R0402#1 2155,2409.37 r0 bottom
R189 "RES_R0402_DISCRETE_0R" R0402#2 1565,2134.37 r90 bottom
R190 "RES_R0402_DISCRETE_22R" R0402#1 2155,2314.37 r0 bottom
R191 "RES_R0402_DISCRETE_22R" R0402#2 2095,2219.37 r90 bottom
R192 "RES_R0402_DISCRETE_100R" R0402#2 2160,3009.37 r90 top
R193 "RES_R0402_DISCRETE_22R" R0402#2 2055,2219.37 r90 bottom
R194 "RES_R0402_DISCRETE_22R" R0402#2 2015,2219.37 r90 bottom
R195 "RES_R0402_DISCRETE_22R" R0402#2 1975,2219.37 r90 bottom
R196 "RES_R0402_DISCRETE_1.1K" R0402#2 2240,3009.37 r90 top
R197 "RES_R0402_DISCRETE_22R" R0402#2 1985,2609.37 r270 bottom
R198 "RES_R0402_DISCRETE_22R" R0402#2 1945,2609.37 r270 bottom
R199 "RES_R0402_DISCRETE_0R" R0402#2 2280,3009.37 r270 top
R200 "RES_R0402_DISCRETE_10K" R0402#2 1905,2609.37 r270 bottom
R201 "RES_R0402_DISCRETE_0R" R0402#2 2320,3009.37 r270 top
R202 "RES_R0402_DISCRETE_1.1K" R0402#2 2360,3009.37 r270 top
R203 "RES_R0402_DISCRETE_20K" R0402#2 1245,2674.37 r90 bottom
R204 "RES_R0402_DISCRETE_20K" R0402#2 1205,2674.37 r90 bottom
R205 "RES_R0402_DISCRETE_10K" R0402#2 1750,3009.37 r90 top
R206 "RES_R0402_DISCRETE_1K" R0402#2 1815,3449.37 r270 bottom
R207 "RES_R0402_DISCRETE_120R" R0402#2 2065,2704.37 r90 bottom
R208 "RES_R0402_DISCRETE_2.2K" R0402#1 2005,2764.37 r0 bottom
R209 "RES_R0402_DISCRETE_20K" R0402#2 1225,2774.37 r0 bottom
R210 "RES_R0603_DISCRETE_0R" R0603#2 1640,2874.37 r0 bottom
R211 "RES_R0402_DISCRETE_NC" R0402#1 1640,2924.37 r0 bottom
R212 "RES_R0402_DISCRETE_100K" R0402#1 1225,2814.37 r0 bottom
R213 "RES_R0603_DISCRETE_0R" R0603#1 1490,2874.37 r0 bottom
R214 "RES_R0402_DISCRETE_4.7K" R0402#2 1395,3009.37 r270 bottom
R215 "RES_R0402_DISCRETE_NC" R0402#2 1490,2924.37 r0 bottom
R216 "RES_R0402_DISCRETE_300K" R0402#2 1800,3009.37 r90 bottom
R217 "RES_R0402_DISCRETE_0R" R0402#2 1810,3704.37 r0 bottom
R218 "RES_R0402_DISCRETE_2.2K" R0402#1 1915,2764.37 r0 bottom
R219 "RES_R0402_DISCRETE_0R" R0402#1 1810,3654.37 r0 bottom
R220 "RES_R0402_DISCRETE_2.2R" R0402#2 1360,3319.37 r270 top
R221 "RES_R0402_DISCRETE_2.2R" R0402#2 1320,3319.37 r270 top
R222 "RES_R0402_DISCRETE_0R" R0402#2 1230,3319.37 r270 top
R223 "RES_R0402_DISCRETE_0R" R0402#2 1270,3319.37 r270 top
R224 "RES_R0402_DISCRETE_0R" R0402#2 1030,3319.37 r270 top
R225 "RES_R0402_DISCRETE_0R" R0402#2 1070,3319.37 r270 top
R226 "RES_R0402_DISCRETE_100K" R0402#2 1220,3329.37 r270 bottom
R227 "RES_R0402_DISCRETE_100K" R0402#2 1340,3329.37 r270 bottom
R228 "RES_R0402_DISCRETE_2M" R0402#2 1320,3389.37 r0 bottom
R229 "RES_R0402_DISCRETE_2M" R0402#1 1240,3389.37 r0 bottom
R230 "RES_R0402_DISCRETE_10K" R0402#2 910,2309.37 r90 bottom
R231 "RES_R0402_DISCRETE_10K" R0402#2 865,2309.37 r90 bottom
R232 "RES_R0402_DISCRETE_10K" R0402#2 955,2309.37 r90 bottom
R233 "RES_R0402_DISCRETE_4.7K" R0402#1 1765,2874.37 r0 bottom
R234 "RES_R0402_DISCRETE_NC" R0402#2 1705,2609.37 r90 bottom
R235 "RES_R0402_DISCRETE_3.4K" R0402#2 1105,3269.37 r0 bottom
R236 "RES_R0402_DISCRETE_1K" R0402#2 785,3229.37 r0 bottom
R237 "RES_R0402_DISCRETE_10K" R0402#1 785,3269.37 r0 bottom
R238 "RES_R0402_DISCRETE_0R" R0402#2 1025,609.37 r0 bottom
R239 "RES_R0402_DISCRETE_100R" R0402#2 245,1310 r90 bottom
R240 "RES_R0402_DISCRETE_0R" R0402#2 4615,2655 r0 bottom
SS1 "SPACER_SMTSO-M2R5_IC_M2.5X1.5MM" SMTSO-M2R5 523.46,2600.44 r0 top
SS2 "SPACER_SMTSO-M2R5_IC_M2.5X1.5MM" SMTSO-M2R5 523.46,789.42 r0 top
SS3 "SPACER_SMTSO-M2R5_IC_M2.5X1.5MM" SMTSO-M2R5 3121.89,789.42 r0 top
SS4 "SPACER_SMTSO-M2R5_IC_M2.5X1.5MM" SMTSO-M2R5 3121.89,2600.44 r0 top
SS5 "SPACER_SMTSO-M2R5_IC_M2.5X3MM" SMTSO-M2R5 4720.61,785.48 r0 top
SS6 "SPACER_SMTSO-M2R5_IC_M2.5X3MM" SMTSO-M2R5 3767.85,785.48 r0 top
SW1 "SW_PB_ESW_SW4-4R20X3R25-SM_IC_SW_PB_ESW" SW4-4R20X3R25-SM 180,472.44 r180 top
SW2 "SW_PB_ESW_SW4-4R20X3R25-SM_IC_SW_PB_ESW" SW4-4R20X3R25-SM 180,645.15 r180 top
SW3 "SW_PB_ESW_SW4-4R20X3R25-SM_IC_SW_PB_ESW" SW4-4R20X3R25-SM 180,817.86 r180 top
SW4 "SW_PB_ESW_SW4-4R20X3R25-SM_IC_SW_PB_ESW" SW4-4R20X3R25-SM 180,990.58 r180 top
SW5 "SW_PB_ESW_SW4-4R20X3R25-SM_IC_SW_PB_ESW" SW4-4R20X3R25-SM 180,1163.29 r180 top
SW6 "SW_PB_ESW_SW4-4R20X3R25-SM_IC_SW_PB_ESW" SW4-4R20X3R25-SM 180,1336 r0 top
